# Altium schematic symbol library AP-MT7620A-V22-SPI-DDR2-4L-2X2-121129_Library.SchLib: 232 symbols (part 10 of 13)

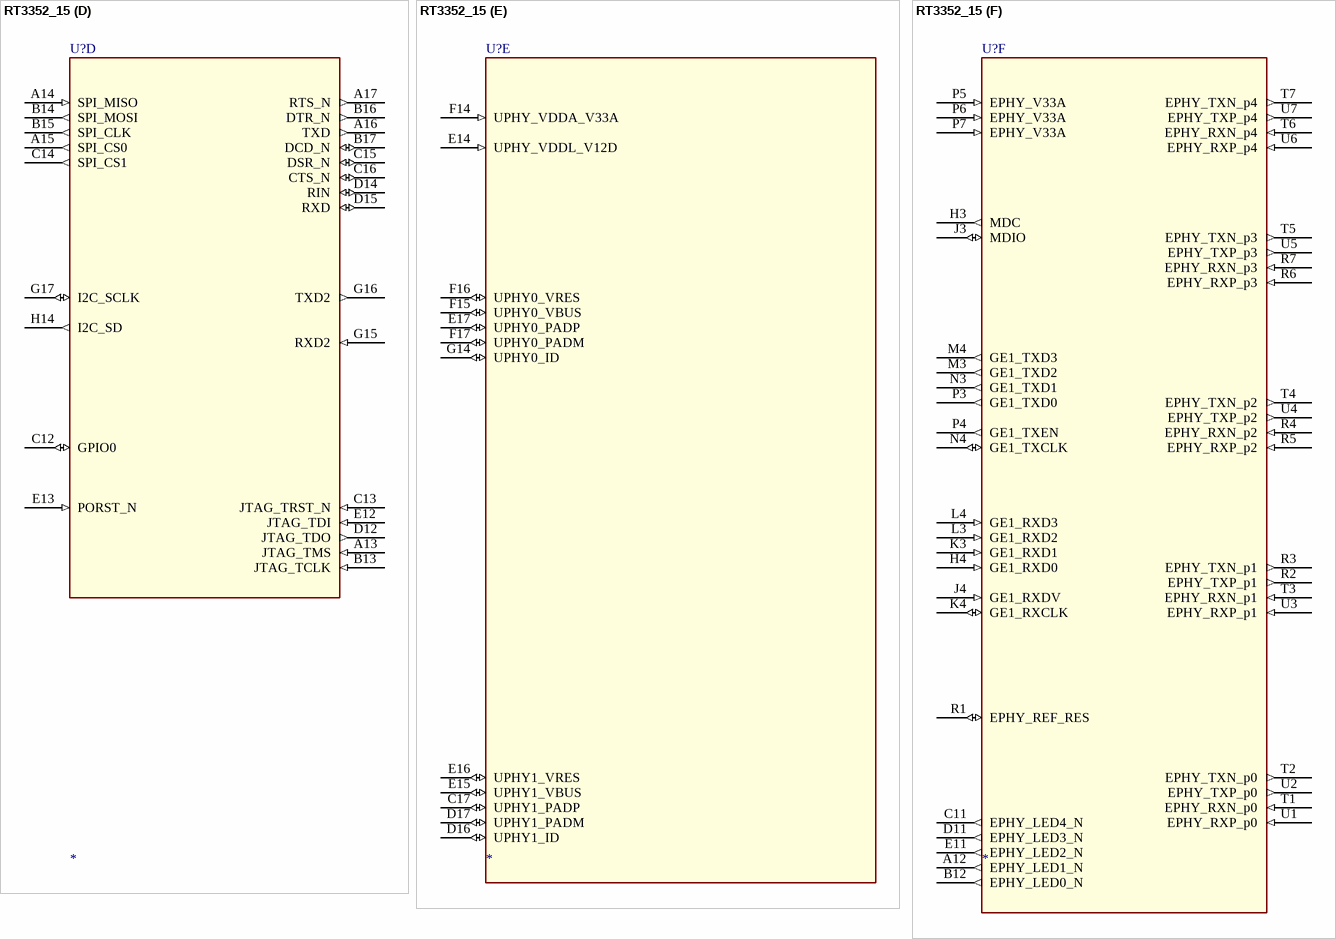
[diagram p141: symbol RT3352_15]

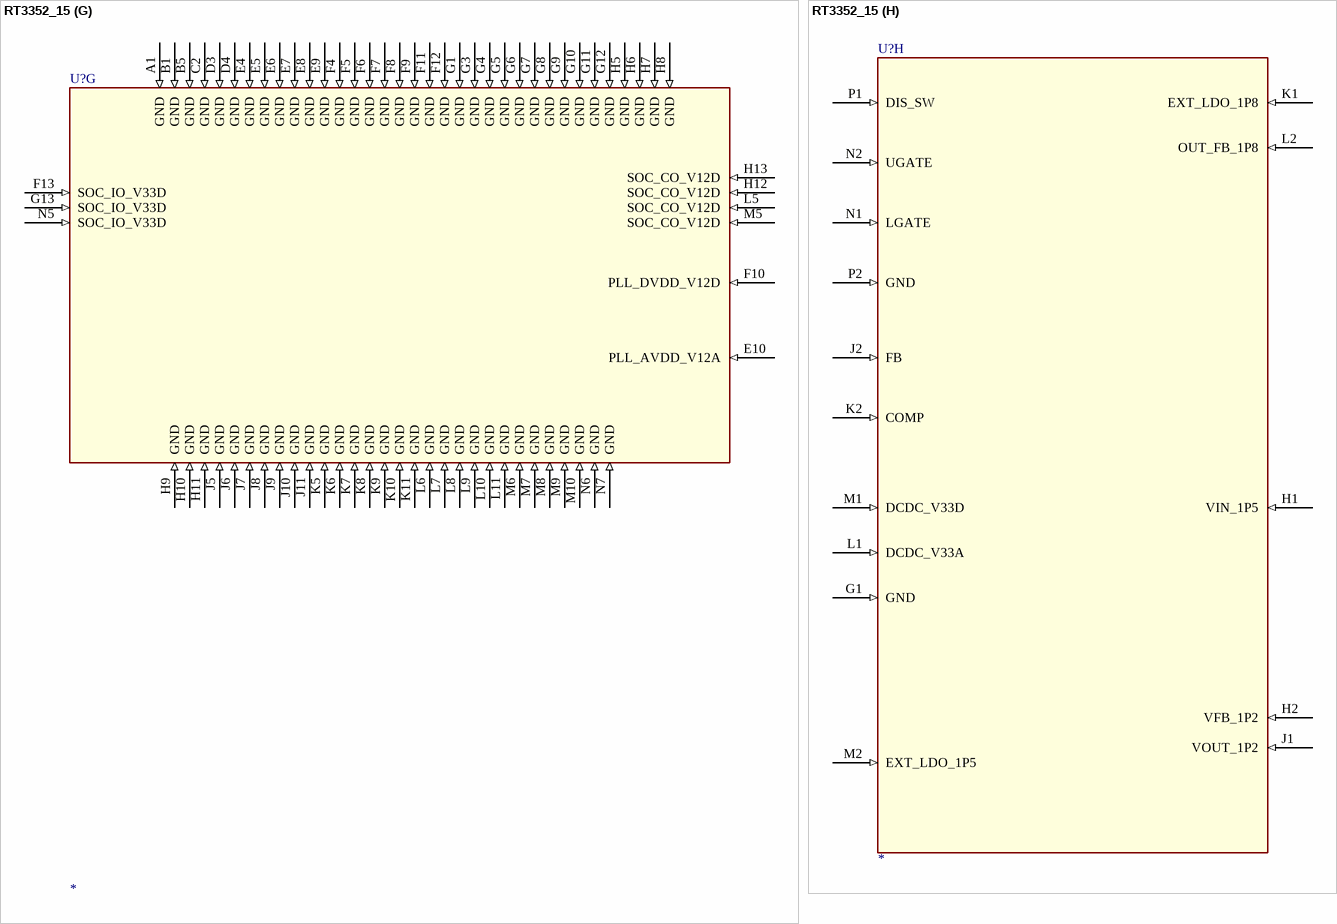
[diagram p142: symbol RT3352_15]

## RT3352_15
designator U?
part A pins: A6 PLL_VC_CAP (in), A7 LDORF_OUT_V12 (out), A8 RF_BB2_V12A (in), A9 ADC_V12 (in), B6 BG_V33A (in), B7 LDORF_IN_VX (in), B8 PLL_X2 (out), B9 PLL_X1 (in), C3 RF0_V12A (in), C4 RF0_IF_V12A (in), C5 VCO_V12A (in), C6 LDOPLL_OUT_V12 (out), C7 BG_RES_12K (in), D5 PLL_V12A (in), D6 RF_BB1_V12A (in), E3 RF1_IF_V12A (in), F3 RF1_V12A (in), G2 RF1_TX_V12A (in)
part B pins: A2 RF0_PA_OUTN (out), A3 RF0_PA_OUTP (out), A4 RF0_2G_INN (in), A5 RF0_2G_INP (in), A10 LNA_PE_G1 (out), A11 ANT_TRNB (out), B2 RF0_PA_V33N (in), B3 RF0_PA_V33P (in), B4 RF0_PA1_V33A (in), B10 LNA_PE_G0 (out), B11 ANT_TRN (out), C1 RF1_2G_INP (in), C8 BASE_TRX_IP (io), C9 BASE_TRX_IN (io), C10 PA_PE_G1 (out), D1 RF1_2G_INN (in), D2 RF1_PA_V33A (in), D7 RF_TSSI_IN (in), D8 BASE_TRX_QP (io), D9 BASE_TRX_QN (io), D10 PA_PE_G0 (out), D13 WLAN_LED_N (out), E1 RF1_PA_OUTP (out), E2 RF1_PA_V33P (in), F1 RF1_PA_OUTN (out), F2 RF1_PA_V33N (in)
part C pins: H15 MD0 (io), H16 MD1 (io), H17 MD2 (io), J12 DDR_IOC_V12D (in), J13 DDR_IOC_V12D (in), J14 MD3 (io), J15 MDQM0 (io), J16 MDQS0 (io), J17 MD6 (io), K12 DDR_IO_V33D (in), K13 DDR_IO_V33D (in), K14 MD8 (io), K15 MD7 (io), K16 MD5 (io), K17 MD4 (io), L12 DDR_IOL_V33D (in), L13 DDR_IOL_V33D (in), L14 MD13 (io), L15 MD10 (io), L16 MD11 (io), L17 MD9 (io), M11 DDR_IO_V33D (in), M12 DDR_IOR_V09D (in), M13 MD15 (io), M14 MD12 (io), M15 MD14 (io), M16 MDQS1 (io), M17 MDQM1 (io), N8 DDR_IO_V33D (in), N9 DDR_IO_V33D (in), N10 DDR_IO_V33D (in), N11 DDR_IO_V33D (in), N12 DDR_IOR_V09D (in), N13 MA0 (io), N14 MA3 (io), N15 MA8 (io), N16 MA10 (io), N17 MA13 (io), P8 MD31 (io), P9 MDQS3 (io), P10 MD22 (io), P11 MDQM2 (io), P12 MD16 (io), P13 MODT (io), P14 MA6 (io), P15 MA4 (io), P16 MA5 (io), P17 MA12 (io), R8 MD30 (io), R9 MD27 (io), R10 MD23 (io), R11 MDQS2 (io), R12 MD17 (io), R13 MCKE (io), R14 MCAS_N (io), R15 MA2 (io), R16 MA7 (io), R17 MA11 (io), T8 MD29 (io), T9 MDQM3 (io), T10 MD24 (io), T11 MD20 (io), T12 MD18 (io), T13 MCK_N (io), T14 MRAS_N (io), T15 MBA0 (io), T16 MA1 (io), T17 MA9 (io), U8 MD28 (io), U9 MD25 (io), U10 MD26 (io), U11 MD21 (io), U12 MD19 (io), U13 MCK_P (io), U14 MWE_N (io), U15 MBA1 (io), U16 MBA2 (io), U17 MCS_N (io)
part D pins: A13 JTAG_TMS (in), A14 SPI_MISO (in), A15 SPI_CS0 (out), A16 TXD (out), A17 RTS_N (out), B13 JTAG_TCLK (in), B14 SPI_MOSI (out), B15 SPI_CLK (out), B16 DTR_N (out), B17 DCD_N (io), C12 GPIO0 (io), C13 JTAG_TRST_N (in), C14 SPI_CS1 (out), C15 DSR_N (io), C16 CTS_N (io), D12 JTAG_TDO (out), D14 RIN (io), D15 RXD (io), E12 JTAG_TDI (in), E13 PORST_N (in), G15 RXD2 (in), G16 TXD2 (out), G17 I2C_SCLK (io), H14 I2C_SD (out)
part E pins: C17 UPHY1_PADP (io), D16 UPHY1_ID (io), D17 UPHY1_PADM (io), E14 UPHY_VDDL_V12D (in), E15 UPHY1_VBUS (io), E16 UPHY1_VRES (io), E17 UPHY0_PADP (io), F14 UPHY_VDDA_V33A (in), F15 UPHY0_VBUS (io), F16 UPHY0_VRES (io), F17 UPHY0_PADM (io), G14 UPHY0_ID (io)
part F pins: A12 EPHY_LED1_N (out), B12 EPHY_LED0_N (out), C11 EPHY_LED4_N (out), D11 EPHY_LED3_N (out), E11 EPHY_LED2_N (out), H3 MDC (out), H4 GE1_RXD0 (in), J3 MDIO (io), J4 GE1_RXDV (in), K3 GE1_RXD1 (in), K4 GE1_RXCLK (io), L3 GE1_RXD2 (in), L4 GE1_RXD3 (in), M3 GE1_TXD2 (out), M4 GE1_TXD3 (out), N3 GE1_TXD1 (out), N4 GE1_TXCLK (io), P3 GE1_TXD0 (out), P4 GE1_TXEN (out), P5 EPHY_V33A (in), P6 EPHY_V33A (in), P7 EPHY_V33A (in), R1 EPHY_REF_RES (io), R2 EPHY_TXP_p1 (out), R3 EPHY_TXN_p1 (out), R4 EPHY_RXN_p2 (in), R5 EPHY_RXP_p2 (in), R6 EPHY_RXP_p3 (in), R7 EPHY_RXN_p3 (in), T1 EPHY_RXN_p0 (in), T2 EPHY_TXN_p0 (out), T3 EPHY_RXN_p1 (in), T4 EPHY_TXN_p2 (out), T5 EPHY_TXN_p3 (out), T6 EPHY_RXN_p4 (in), T7 EPHY_TXN_p4 (out), U1 EPHY_RXP_p0 (in), U2 EPHY_TXP_p0 (out), U3 EPHY_RXP_p1 (in), U4 EPHY_TXP_p2 (out), U5 EPHY_TXP_p3 (out), U6 EPHY_RXP_p4 (in), U7 EPHY_TXP_p4 (out)
part G pins: A1 GND (in), B1 GND (in), B5 GND (in), C2 GND (in), D3 GND (in), D4 GND (in), E4 GND (in), E5 GND (in), E6 GND (in), E7 GND (in), E8 GND (in), E9 GND (in), E10 PLL_AVDD_V12A (in), F4 GND (in), F5 GND (in), F6 GND (in), F7 GND (in), F8 GND (in), F9 GND (in), F10 PLL_DVDD_V12D (in), F11 GND (in), F12 GND (in), F13 SOC_IO_V33D (in), G1 GND (in), G3 GND (in), G4 GND (in), G5 GND (in), G6 GND (in), G7 GND (in), G8 GND (in), G9 GND (in), G10 GND (in), G11 GND (in), G12 GND (in), G13 SOC_IO_V33D (in), H5 GND (in), H6 GND (in), H7 GND (in), H8 GND (in), H9 GND (in), H10 GND (in), H11 GND (in), H12 SOC_CO_V12D (in), H13 SOC_CO_V12D (in), J5 GND (in), J6 GND (in), J7 GND (in), J8 GND (in), J9 GND (in), J10 GND (in), J11 GND (in), K5 GND (in), K6 GND (in), K7 GND (in), K8 GND (in), K9 GND (in), K10 GND (in), K11 GND (in), L5 SOC_CO_V12D (in), L6 GND (in), L7 GND (in), L8 GND (in), L9 GND (in), L10 GND (in), L11 GND (in), M5 SOC_CO_V12D (in), M6 GND (in), M7 GND (in), M8 GND (in), M9 GND (in), M10 GND (in), N5 SOC_IO_V33D (in), N6 GND (in), N7 GND (in)
part H pins: G1 GND (in), H1 VIN_1P5 (in), H2 VFB_1P2 (in), J1 VOUT_1P2 (in), J2 FB (in), K1 EXT_LDO_1P8 (in), K2 COMP (in), L1 DCDC_V33A (in), L2 OUT_FB_1P8 (in), M1 DCDC_V33D (in), M2 EXT_LDO_1P5 (in), N1 LGATE (in), N2 UGATE (in), P1 DIS_SW (in), P2 GND (in)

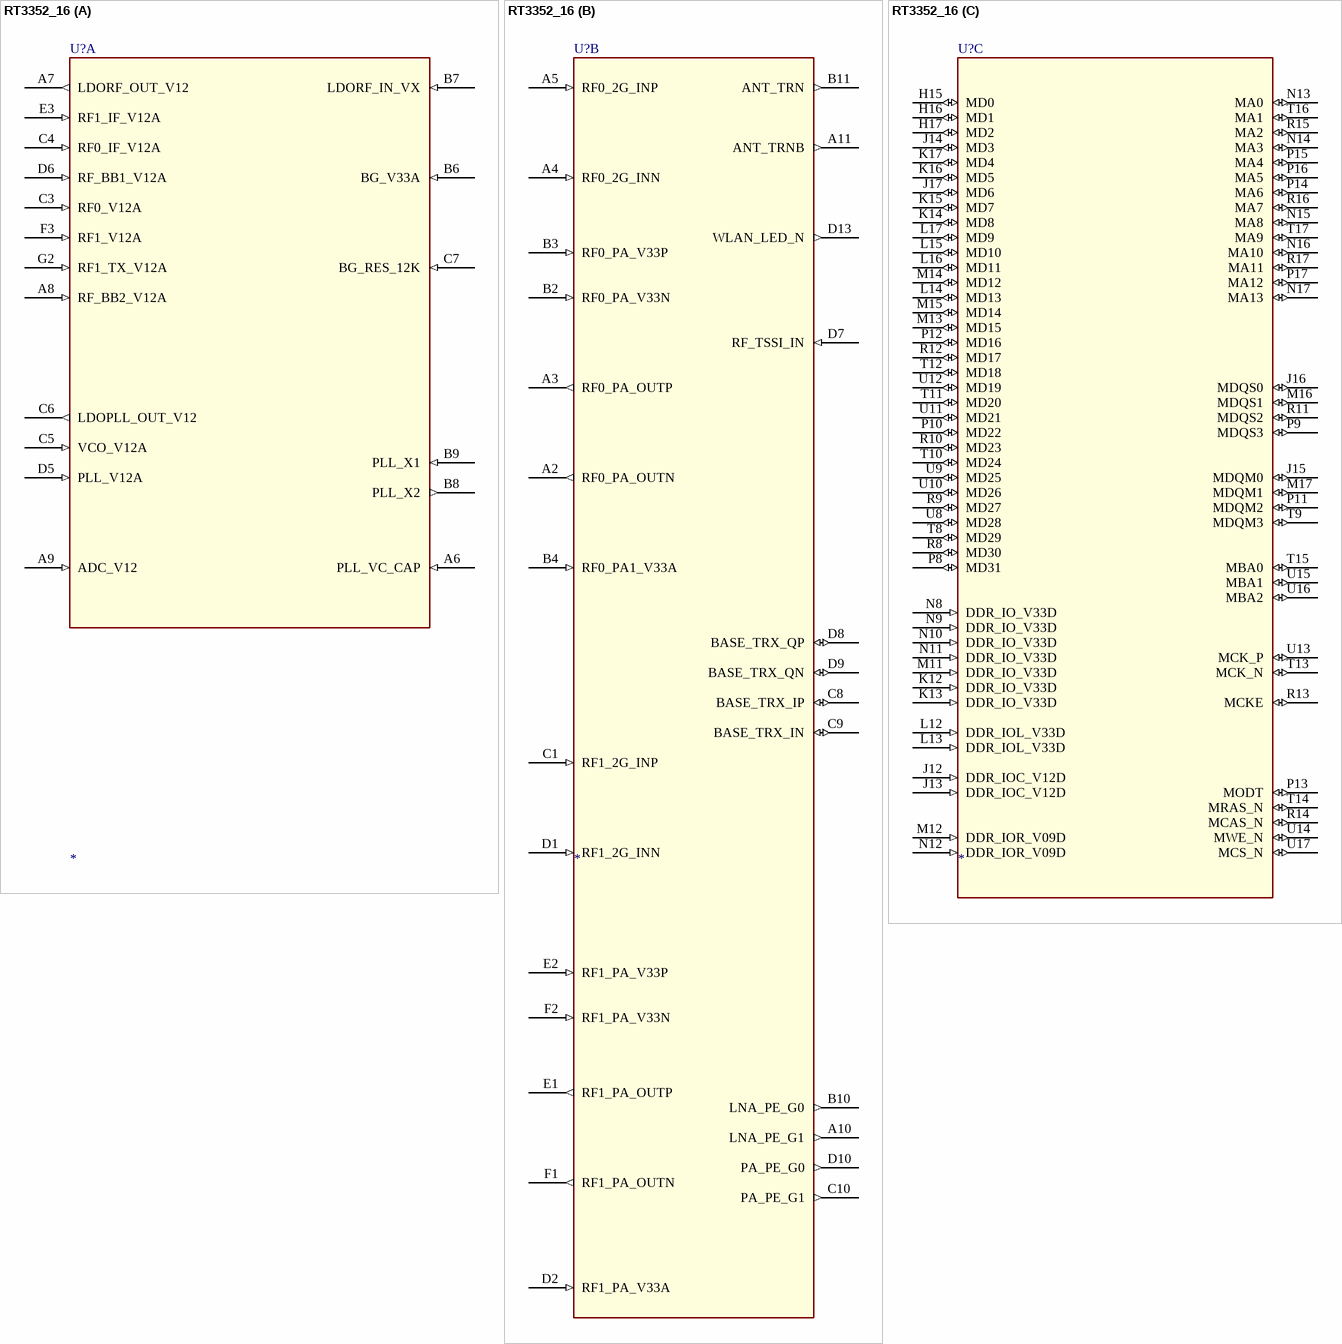
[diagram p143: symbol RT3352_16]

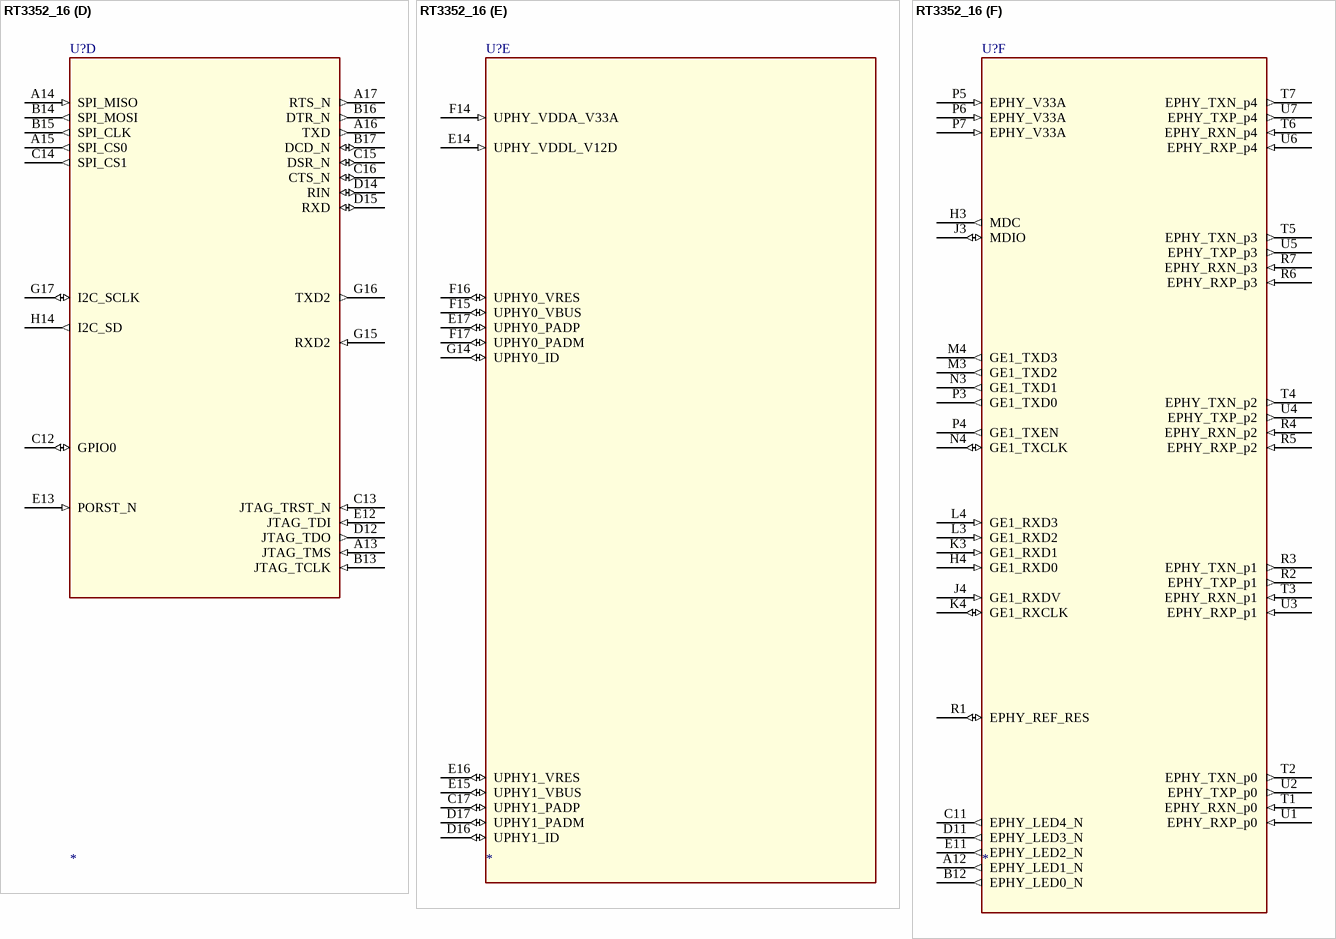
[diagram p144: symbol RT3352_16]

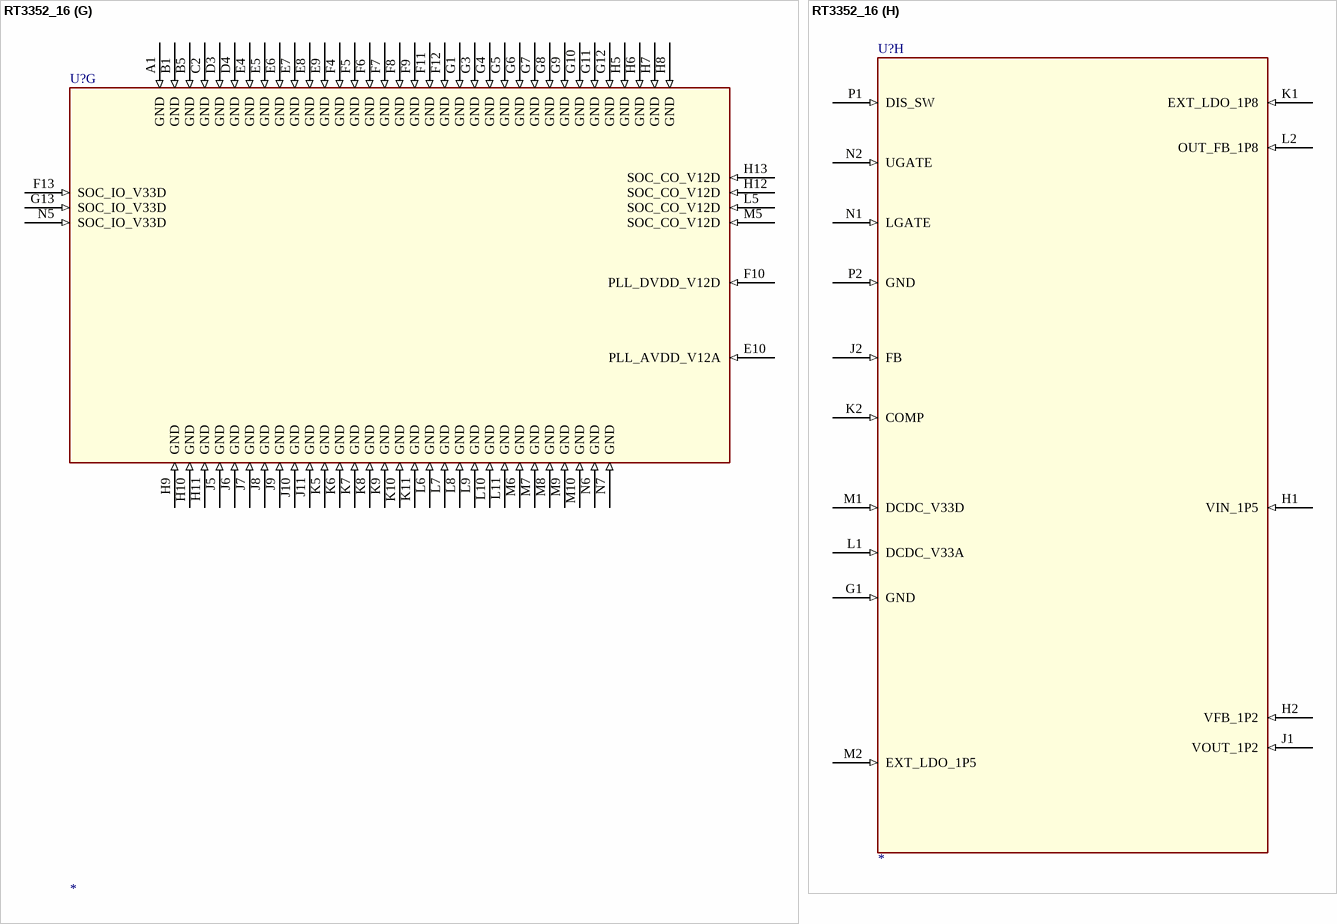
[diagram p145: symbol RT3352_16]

## RT3352_16
designator U?
part A pins: A6 PLL_VC_CAP (in), A7 LDORF_OUT_V12 (out), A8 RF_BB2_V12A (in), A9 ADC_V12 (in), B6 BG_V33A (in), B7 LDORF_IN_VX (in), B8 PLL_X2 (out), B9 PLL_X1 (in), C3 RF0_V12A (in), C4 RF0_IF_V12A (in), C5 VCO_V12A (in), C6 LDOPLL_OUT_V12 (out), C7 BG_RES_12K (in), D5 PLL_V12A (in), D6 RF_BB1_V12A (in), E3 RF1_IF_V12A (in), F3 RF1_V12A (in), G2 RF1_TX_V12A (in)
part B pins: A2 RF0_PA_OUTN (out), A3 RF0_PA_OUTP (out), A4 RF0_2G_INN (in), A5 RF0_2G_INP (in), A10 LNA_PE_G1 (out), A11 ANT_TRNB (out), B2 RF0_PA_V33N (in), B3 RF0_PA_V33P (in), B4 RF0_PA1_V33A (in), B10 LNA_PE_G0 (out), B11 ANT_TRN (out), C1 RF1_2G_INP (in), C8 BASE_TRX_IP (io), C9 BASE_TRX_IN (io), C10 PA_PE_G1 (out), D1 RF1_2G_INN (in), D2 RF1_PA_V33A (in), D7 RF_TSSI_IN (in), D8 BASE_TRX_QP (io), D9 BASE_TRX_QN (io), D10 PA_PE_G0 (out), D13 WLAN_LED_N (out), E1 RF1_PA_OUTP (out), E2 RF1_PA_V33P (in), F1 RF1_PA_OUTN (out), F2 RF1_PA_V33N (in)
part C pins: H15 MD0 (io), H16 MD1 (io), H17 MD2 (io), J12 DDR_IOC_V12D (in), J13 DDR_IOC_V12D (in), J14 MD3 (io), J15 MDQM0 (io), J16 MDQS0 (io), J17 MD6 (io), K12 DDR_IO_V33D (in), K13 DDR_IO_V33D (in), K14 MD8 (io), K15 MD7 (io), K16 MD5 (io), K17 MD4 (io), L12 DDR_IOL_V33D (in), L13 DDR_IOL_V33D (in), L14 MD13 (io), L15 MD10 (io), L16 MD11 (io), L17 MD9 (io), M11 DDR_IO_V33D (in), M12 DDR_IOR_V09D (in), M13 MD15 (io), M14 MD12 (io), M15 MD14 (io), M16 MDQS1 (io), M17 MDQM1 (io), N8 DDR_IO_V33D (in), N9 DDR_IO_V33D (in), N10 DDR_IO_V33D (in), N11 DDR_IO_V33D (in), N12 DDR_IOR_V09D (in), N13 MA0 (io), N14 MA3 (io), N15 MA8 (io), N16 MA10 (io), N17 MA13 (io), P8 MD31 (io), P9 MDQS3 (io), P10 MD22 (io), P11 MDQM2 (io), P12 MD16 (io), P13 MODT (io), P14 MA6 (io), P15 MA4 (io), P16 MA5 (io), P17 MA12 (io), R8 MD30 (io), R9 MD27 (io), R10 MD23 (io), R11 MDQS2 (io), R12 MD17 (io), R13 MCKE (io), R14 MCAS_N (io), R15 MA2 (io), R16 MA7 (io), R17 MA11 (io), T8 MD29 (io), T9 MDQM3 (io), T10 MD24 (io), T11 MD20 (io), T12 MD18 (io), T13 MCK_N (io), T14 MRAS_N (io), T15 MBA0 (io), T16 MA1 (io), T17 MA9 (io), U8 MD28 (io), U9 MD25 (io), U10 MD26 (io), U11 MD21 (io), U12 MD19 (io), U13 MCK_P (io), U14 MWE_N (io), U15 MBA1 (io), U16 MBA2 (io), U17 MCS_N (io)
part D pins: A13 JTAG_TMS (in), A14 SPI_MISO (in), A15 SPI_CS0 (out), A16 TXD (out), A17 RTS_N (out), B13 JTAG_TCLK (in), B14 SPI_MOSI (out), B15 SPI_CLK (out), B16 DTR_N (out), B17 DCD_N (io), C12 GPIO0 (io), C13 JTAG_TRST_N (in), C14 SPI_CS1 (out), C15 DSR_N (io), C16 CTS_N (io), D12 JTAG_TDO (out), D14 RIN (io), D15 RXD (io), E12 JTAG_TDI (in), E13 PORST_N (in), G15 RXD2 (in), G16 TXD2 (out), G17 I2C_SCLK (io), H14 I2C_SD (out)
part E pins: C17 UPHY1_PADP (io), D16 UPHY1_ID (io), D17 UPHY1_PADM (io), E14 UPHY_VDDL_V12D (in), E15 UPHY1_VBUS (io), E16 UPHY1_VRES (io), E17 UPHY0_PADP (io), F14 UPHY_VDDA_V33A (in), F15 UPHY0_VBUS (io), F16 UPHY0_VRES (io), F17 UPHY0_PADM (io), G14 UPHY0_ID (io)
part F pins: A12 EPHY_LED1_N (out), B12 EPHY_LED0_N (out), C11 EPHY_LED4_N (out), D11 EPHY_LED3_N (out), E11 EPHY_LED2_N (out), H3 MDC (out), H4 GE1_RXD0 (in), J3 MDIO (io), J4 GE1_RXDV (in), K3 GE1_RXD1 (in), K4 GE1_RXCLK (io), L3 GE1_RXD2 (in), L4 GE1_RXD3 (in), M3 GE1_TXD2 (out), M4 GE1_TXD3 (out), N3 GE1_TXD1 (out), N4 GE1_TXCLK (io), P3 GE1_TXD0 (out), P4 GE1_TXEN (out), P5 EPHY_V33A (in), P6 EPHY_V33A (in), P7 EPHY_V33A (in), R1 EPHY_REF_RES (io), R2 EPHY_TXP_p1 (out), R3 EPHY_TXN_p1 (out), R4 EPHY_RXN_p2 (in), R5 EPHY_RXP_p2 (in), R6 EPHY_RXP_p3 (in), R7 EPHY_RXN_p3 (in), T1 EPHY_RXN_p0 (in), T2 EPHY_TXN_p0 (out), T3 EPHY_RXN_p1 (in), T4 EPHY_TXN_p2 (out), T5 EPHY_TXN_p3 (out), T6 EPHY_RXN_p4 (in), T7 EPHY_TXN_p4 (out), U1 EPHY_RXP_p0 (in), U2 EPHY_TXP_p0 (out), U3 EPHY_RXP_p1 (in), U4 EPHY_TXP_p2 (out), U5 EPHY_TXP_p3 (out), U6 EPHY_RXP_p4 (in), U7 EPHY_TXP_p4 (out)
part G pins: A1 GND (in), B1 GND (in), B5 GND (in), C2 GND (in), D3 GND (in), D4 GND (in), E4 GND (in), E5 GND (in), E6 GND (in), E7 GND (in), E8 GND (in), E9 GND (in), E10 PLL_AVDD_V12A (in), F4 GND (in), F5 GND (in), F6 GND (in), F7 GND (in), F8 GND (in), F9 GND (in), F10 PLL_DVDD_V12D (in), F11 GND (in), F12 GND (in), F13 SOC_IO_V33D (in), G1 GND (in), G3 GND (in), G4 GND (in), G5 GND (in), G6 GND (in), G7 GND (in), G8 GND (in), G9 GND (in), G10 GND (in), G11 GND (in), G12 GND (in), G13 SOC_IO_V33D (in), H5 GND (in), H6 GND (in), H7 GND (in), H8 GND (in), H9 GND (in), H10 GND (in), H11 GND (in), H12 SOC_CO_V12D (in), H13 SOC_CO_V12D (in), J5 GND (in), J6 GND (in), J7 GND (in), J8 GND (in), J9 GND (in), J10 GND (in), J11 GND (in), K5 GND (in), K6 GND (in), K7 GND (in), K8 GND (in), K9 GND (in), K10 GND (in), K11 GND (in), L5 SOC_CO_V12D (in), L6 GND (in), L7 GND (in), L8 GND (in), L9 GND (in), L10 GND (in), L11 GND (in), M5 SOC_CO_V12D (in), M6 GND (in), M7 GND (in), M8 GND (in), M9 GND (in), M10 GND (in), N5 SOC_IO_V33D (in), N6 GND (in), N7 GND (in)
part H pins: G1 GND (in), H1 VIN_1P5 (in), H2 VFB_1P2 (in), J1 VOUT_1P2 (in), J2 FB (in), K1 EXT_LDO_1P8 (in), K2 COMP (in), L1 DCDC_V33A (in), L2 OUT_FB_1P8 (in), M1 DCDC_V33D (in), M2 EXT_LDO_1P5 (in), N1 LGATE (in), N2 UGATE (in), P1 DIS_SW (in), P2 GND (in)

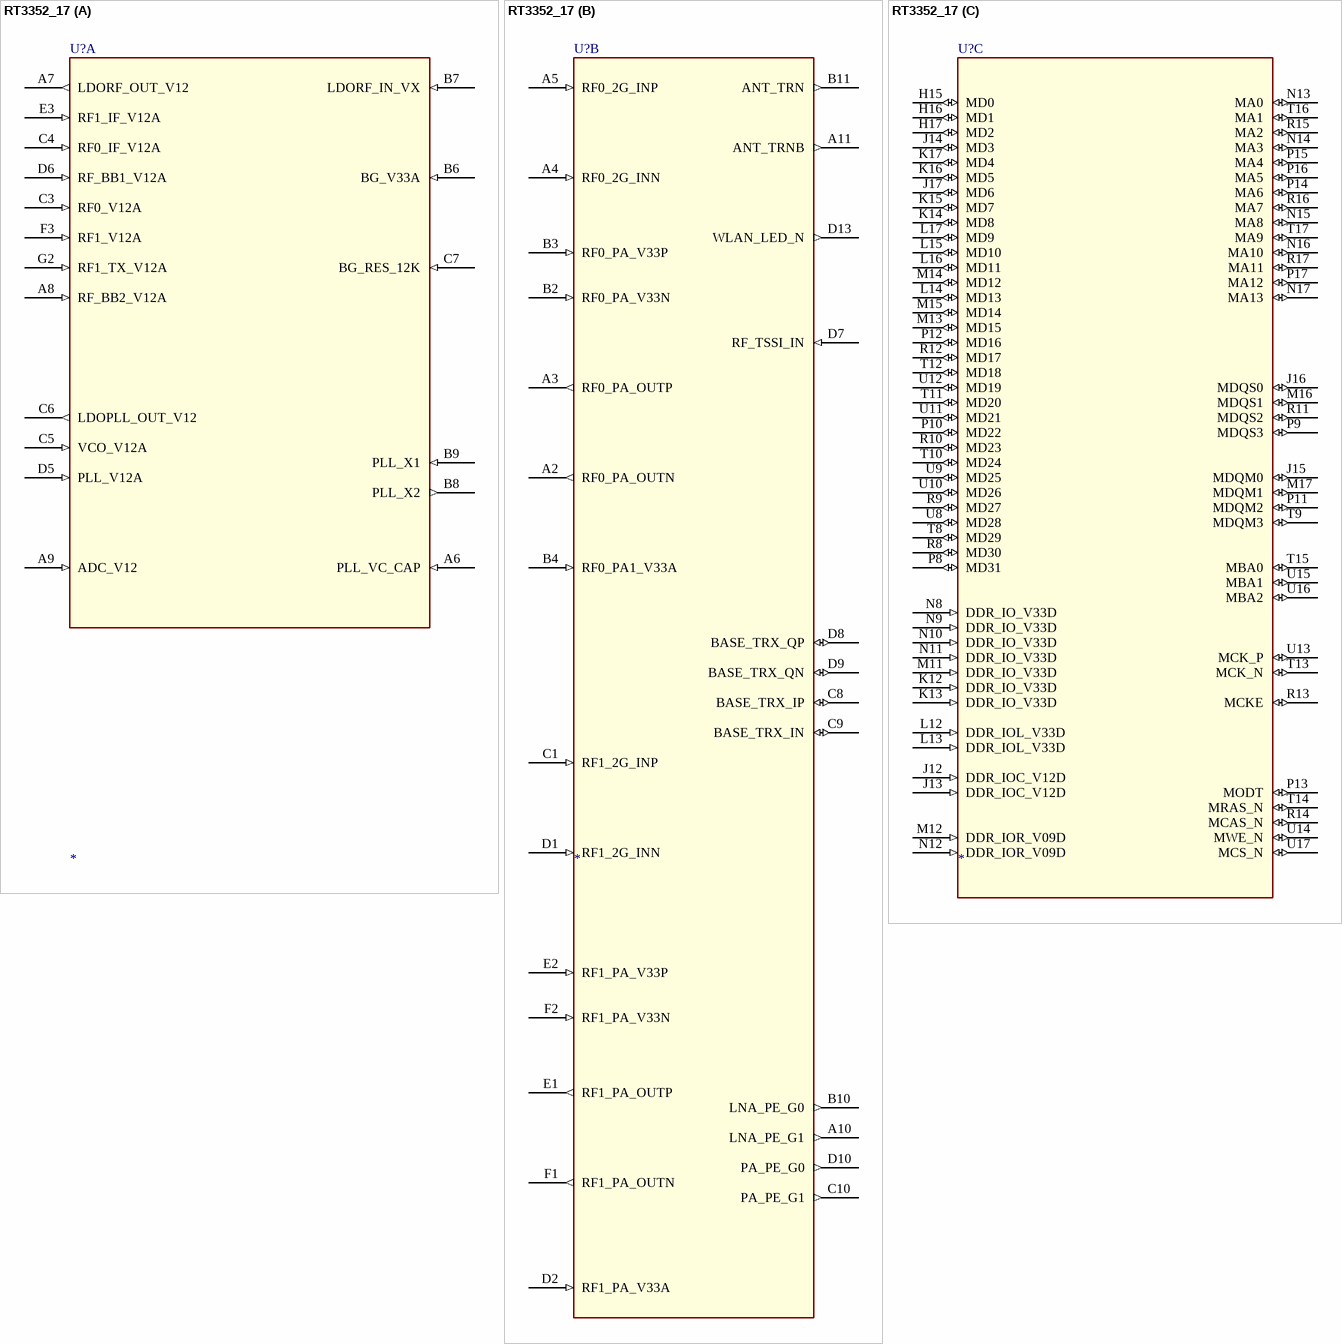
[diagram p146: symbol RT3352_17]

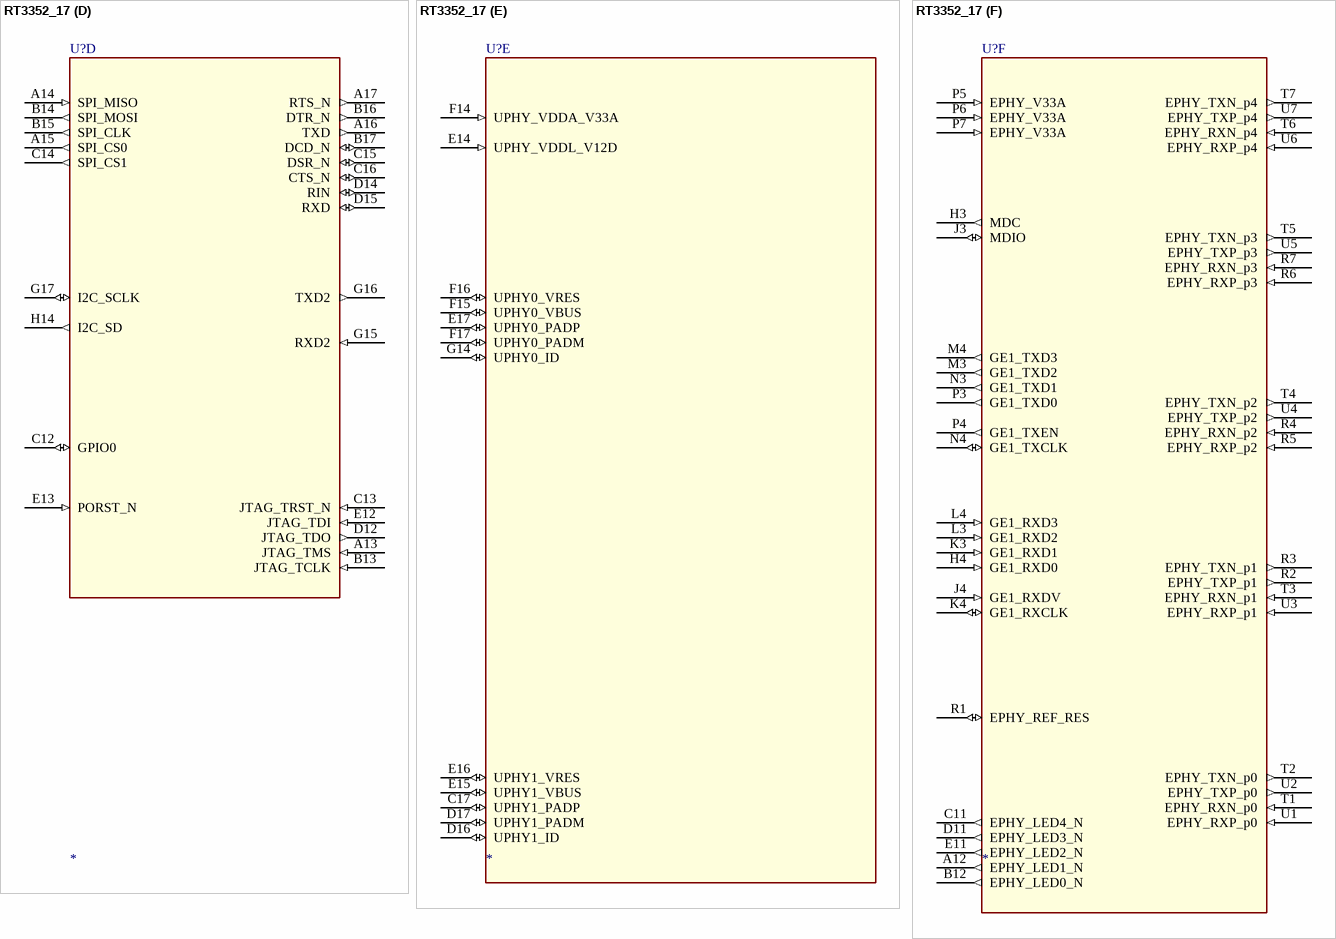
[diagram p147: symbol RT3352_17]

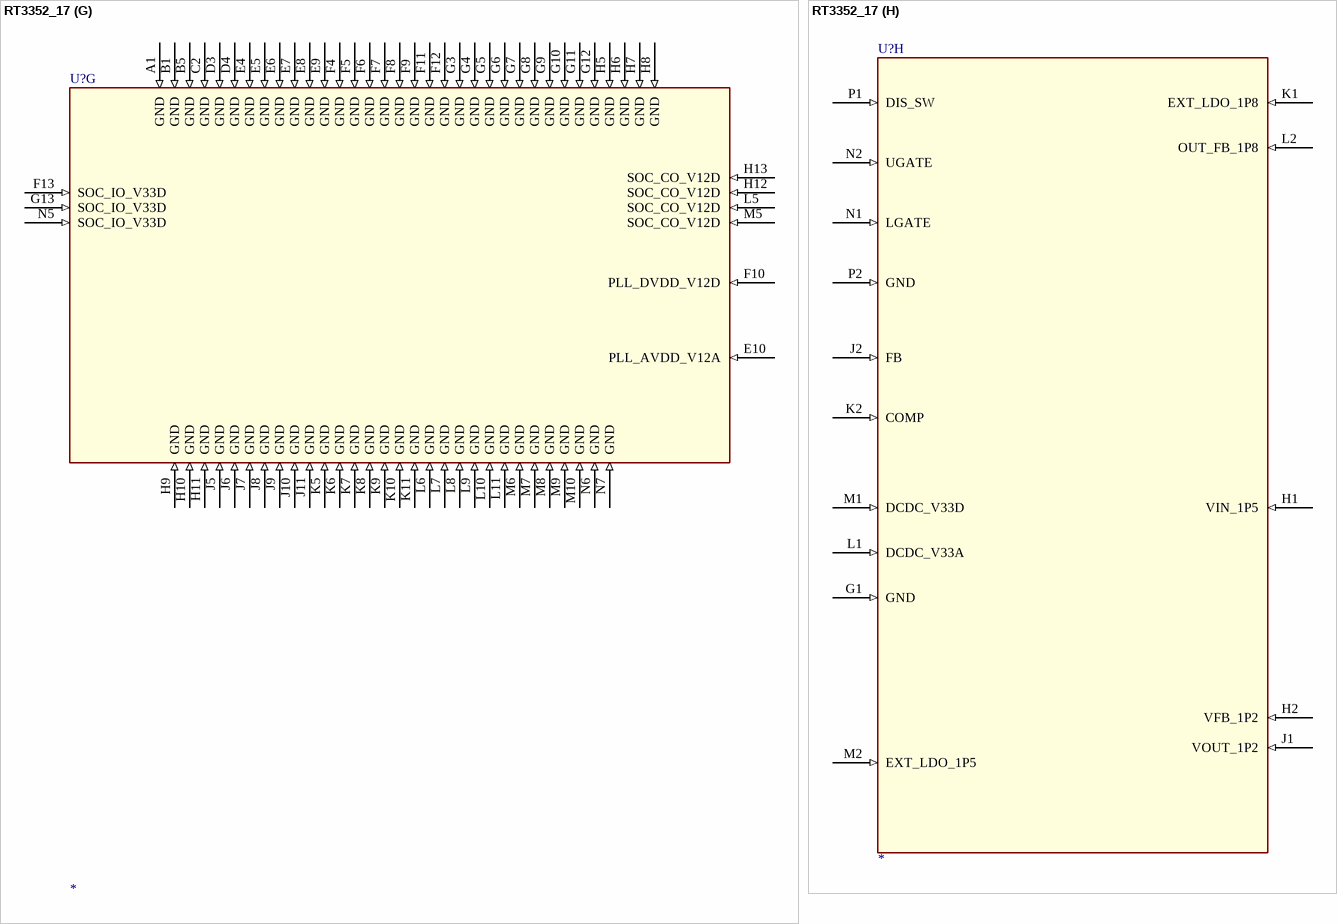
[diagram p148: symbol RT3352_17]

## RT3352_17
designator U?
part A pins: A6 PLL_VC_CAP (in), A7 LDORF_OUT_V12 (out), A8 RF_BB2_V12A (in), A9 ADC_V12 (in), B6 BG_V33A (in), B7 LDORF_IN_VX (in), B8 PLL_X2 (out), B9 PLL_X1 (in), C3 RF0_V12A (in), C4 RF0_IF_V12A (in), C5 VCO_V12A (in), C6 LDOPLL_OUT_V12 (out), C7 BG_RES_12K (in), D5 PLL_V12A (in), D6 RF_BB1_V12A (in), E3 RF1_IF_V12A (in), F3 RF1_V12A (in), G2 RF1_TX_V12A (in)
part B pins: A2 RF0_PA_OUTN (out), A3 RF0_PA_OUTP (out), A4 RF0_2G_INN (in), A5 RF0_2G_INP (in), A10 LNA_PE_G1 (out), A11 ANT_TRNB (out), B2 RF0_PA_V33N (in), B3 RF0_PA_V33P (in), B4 RF0_PA1_V33A (in), B10 LNA_PE_G0 (out), B11 ANT_TRN (out), C1 RF1_2G_INP (in), C8 BASE_TRX_IP (io), C9 BASE_TRX_IN (io), C10 PA_PE_G1 (out), D1 RF1_2G_INN (in), D2 RF1_PA_V33A (in), D7 RF_TSSI_IN (in), D8 BASE_TRX_QP (io), D9 BASE_TRX_QN (io), D10 PA_PE_G0 (out), D13 WLAN_LED_N (out), E1 RF1_PA_OUTP (out), E2 RF1_PA_V33P (in), F1 RF1_PA_OUTN (out), F2 RF1_PA_V33N (in)
part C pins: H15 MD0 (io), H16 MD1 (io), H17 MD2 (io), J12 DDR_IOC_V12D (in), J13 DDR_IOC_V12D (in), J14 MD3 (io), J15 MDQM0 (io), J16 MDQS0 (io), J17 MD6 (io), K12 DDR_IO_V33D (in), K13 DDR_IO_V33D (in), K14 MD8 (io), K15 MD7 (io), K16 MD5 (io), K17 MD4 (io), L12 DDR_IOL_V33D (in), L13 DDR_IOL_V33D (in), L14 MD13 (io), L15 MD10 (io), L16 MD11 (io), L17 MD9 (io), M11 DDR_IO_V33D (in), M12 DDR_IOR_V09D (in), M13 MD15 (io), M14 MD12 (io), M15 MD14 (io), M16 MDQS1 (io), M17 MDQM1 (io), N8 DDR_IO_V33D (in), N9 DDR_IO_V33D (in), N10 DDR_IO_V33D (in), N11 DDR_IO_V33D (in), N12 DDR_IOR_V09D (in), N13 MA0 (io), N14 MA3 (io), N15 MA8 (io), N16 MA10 (io), N17 MA13 (io), P8 MD31 (io), P9 MDQS3 (io), P10 MD22 (io), P11 MDQM2 (io), P12 MD16 (io), P13 MODT (io), P14 MA6 (io), P15 MA4 (io), P16 MA5 (io), P17 MA12 (io), R8 MD30 (io), R9 MD27 (io), R10 MD23 (io), R11 MDQS2 (io), R12 MD17 (io), R13 MCKE (io), R14 MCAS_N (io), R15 MA2 (io), R16 MA7 (io), R17 MA11 (io), T8 MD29 (io), T9 MDQM3 (io), T10 MD24 (io), T11 MD20 (io), T12 MD18 (io), T13 MCK_N (io), T14 MRAS_N (io), T15 MBA0 (io), T16 MA1 (io), T17 MA9 (io), U8 MD28 (io), U9 MD25 (io), U10 MD26 (io), U11 MD21 (io), U12 MD19 (io), U13 MCK_P (io), U14 MWE_N (io), U15 MBA1 (io), U16 MBA2 (io), U17 MCS_N (io)
part D pins: A13 JTAG_TMS (in), A14 SPI_MISO (in), A15 SPI_CS0 (out), A16 TXD (out), A17 RTS_N (out), B13 JTAG_TCLK (in), B14 SPI_MOSI (out), B15 SPI_CLK (out), B16 DTR_N (out), B17 DCD_N (io), C12 GPIO0 (io), C13 JTAG_TRST_N (in), C14 SPI_CS1 (out), C15 DSR_N (io), C16 CTS_N (io), D12 JTAG_TDO (out), D14 RIN (io), D15 RXD (io), E12 JTAG_TDI (in), E13 PORST_N (in), G15 RXD2 (in), G16 TXD2 (out), G17 I2C_SCLK (io), H14 I2C_SD (out)
part E pins: C17 UPHY1_PADP (io), D16 UPHY1_ID (io), D17 UPHY1_PADM (io), E14 UPHY_VDDL_V12D (in), E15 UPHY1_VBUS (io), E16 UPHY1_VRES (io), E17 UPHY0_PADP (io), F14 UPHY_VDDA_V33A (in), F15 UPHY0_VBUS (io), F16 UPHY0_VRES (io), F17 UPHY0_PADM (io), G14 UPHY0_ID (io)
part F pins: A12 EPHY_LED1_N (out), B12 EPHY_LED0_N (out), C11 EPHY_LED4_N (out), D11 EPHY_LED3_N (out), E11 EPHY_LED2_N (out), H3 MDC (out), H4 GE1_RXD0 (in), J3 MDIO (io), J4 GE1_RXDV (in), K3 GE1_RXD1 (in), K4 GE1_RXCLK (io), L3 GE1_RXD2 (in), L4 GE1_RXD3 (in), M3 GE1_TXD2 (out), M4 GE1_TXD3 (out), N3 GE1_TXD1 (out), N4 GE1_TXCLK (io), P3 GE1_TXD0 (out), P4 GE1_TXEN (out), P5 EPHY_V33A (in), P6 EPHY_V33A (in), P7 EPHY_V33A (in), R1 EPHY_REF_RES (io), R2 EPHY_TXP_p1 (out), R3 EPHY_TXN_p1 (out), R4 EPHY_RXN_p2 (in), R5 EPHY_RXP_p2 (in), R6 EPHY_RXP_p3 (in), R7 EPHY_RXN_p3 (in), T1 EPHY_RXN_p0 (in), T2 EPHY_TXN_p0 (out), T3 EPHY_RXN_p1 (in), T4 EPHY_TXN_p2 (out), T5 EPHY_TXN_p3 (out), T6 EPHY_RXN_p4 (in), T7 EPHY_TXN_p4 (out), U1 EPHY_RXP_p0 (in), U2 EPHY_TXP_p0 (out), U3 EPHY_RXP_p1 (in), U4 EPHY_TXP_p2 (out), U5 EPHY_TXP_p3 (out), U6 EPHY_RXP_p4 (in), U7 EPHY_TXP_p4 (out)
part G pins: A1 GND (in), B1 GND (in), B5 GND (in), C2 GND (in), D3 GND (in), D4 GND (in), E4 GND (in), E5 GND (in), E6 GND (in), E7 GND (in), E8 GND (in), E9 GND (in), E10 PLL_AVDD_V12A (in), F4 GND (in), F5 GND (in), F6 GND (in), F7 GND (in), F8 GND (in), F9 GND (in), F10 PLL_DVDD_V12D (in), F11 GND (in), F12 GND (in), F13 SOC_IO_V33D (in), G3 GND (in), G4 GND (in), G5 GND (in), G6 GND (in), G7 GND (in), G8 GND (in), G9 GND (in), G10 GND (in), G11 GND (in), G12 GND (in), G13 SOC_IO_V33D (in), H5 GND (in), H6 GND (in), H7 GND (in), H8 GND (in), H9 GND (in), H10 GND (in), H11 GND (in), H12 SOC_CO_V12D (in), H13 SOC_CO_V12D (in), J5 GND (in), J6 GND (in), J7 GND (in), J8 GND (in), J9 GND (in), J10 GND (in), J11 GND (in), K5 GND (in), K6 GND (in), K7 GND (in), K8 GND (in), K9 GND (in), K10 GND (in), K11 GND (in), L5 SOC_CO_V12D (in), L6 GND (in), L7 GND (in), L8 GND (in), L9 GND (in), L10 GND (in), L11 GND (in), M5 SOC_CO_V12D (in), M6 GND (in), M7 GND (in), M8 GND (in), M9 GND (in), M10 GND (in), N5 SOC_IO_V33D (in), N6 GND (in), N7 GND (in)
part H pins: G1 GND (in), H1 VIN_1P5 (in), H2 VFB_1P2 (in), J1 VOUT_1P2 (in), J2 FB (in), K1 EXT_LDO_1P8 (in), K2 COMP (in), L1 DCDC_V33A (in), L2 OUT_FB_1P8 (in), M1 DCDC_V33D (in), M2 EXT_LDO_1P5 (in), N1 LGATE (in), N2 UGATE (in), P1 DIS_SW (in), P2 GND (in)

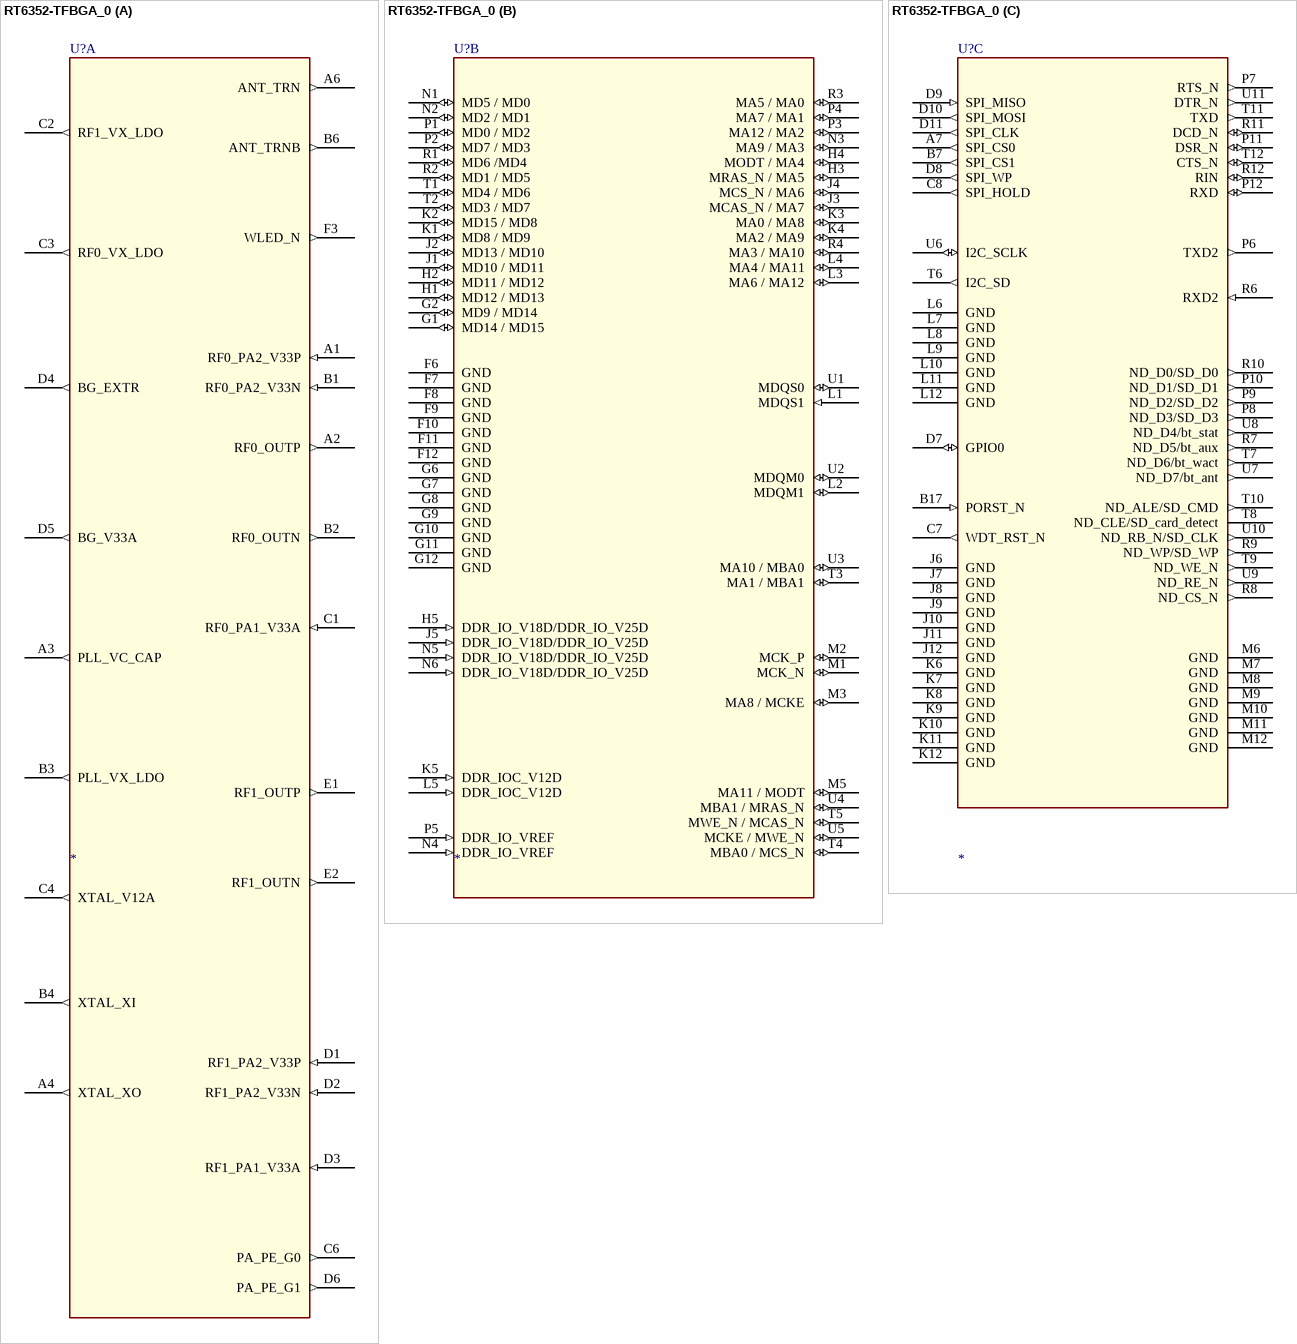
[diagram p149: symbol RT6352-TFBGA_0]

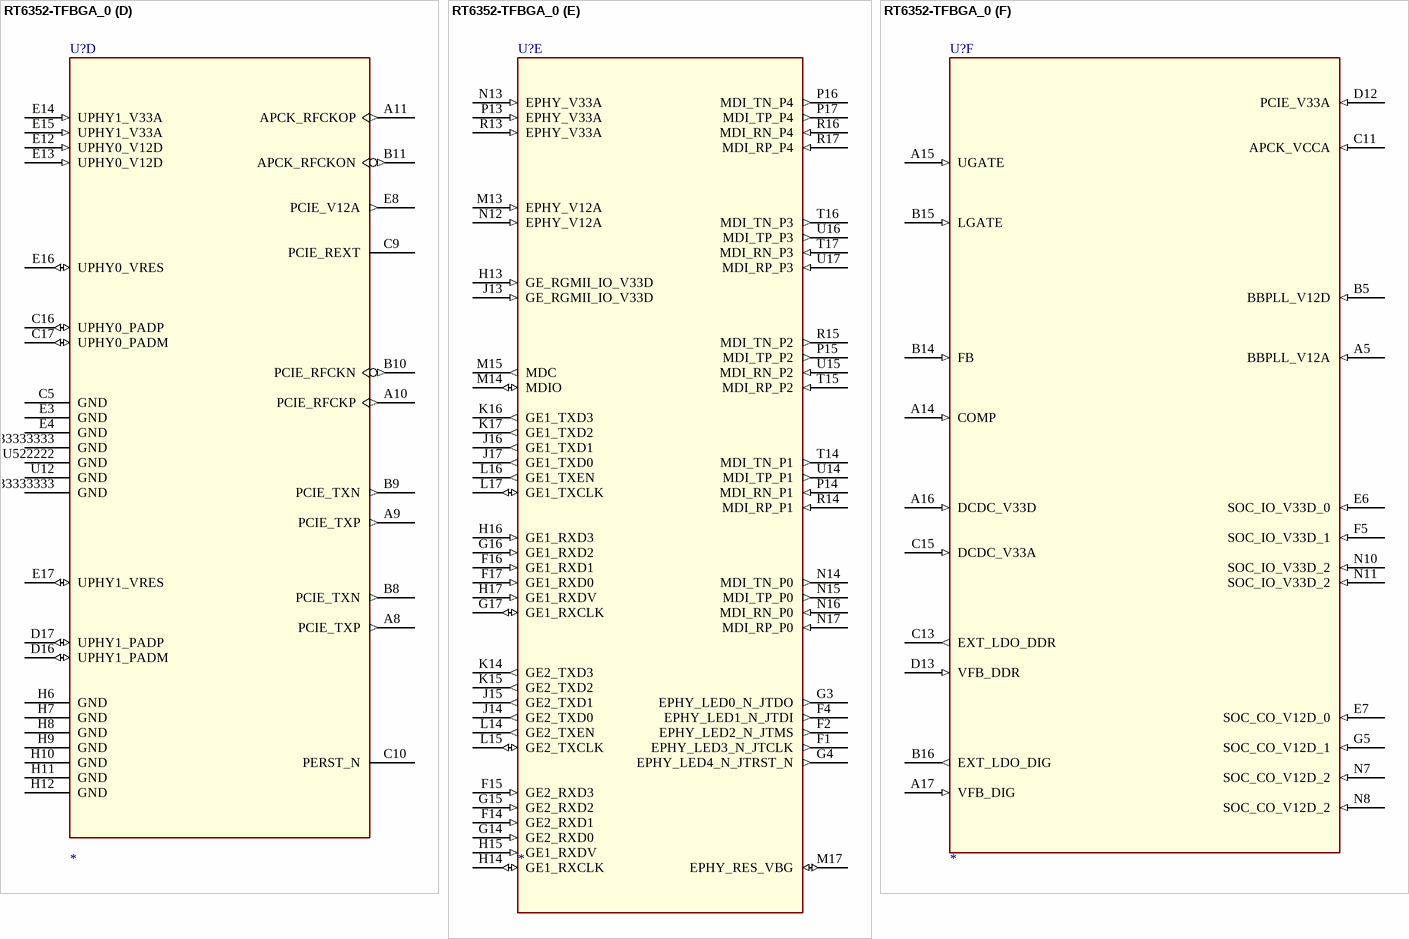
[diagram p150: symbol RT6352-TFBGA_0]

## RT6352-TFBGA_0
designator U?
footprint RT6352/BGA289/P0.65/12X12
part A pins: A1 RF0_PA2_V33P (in), A2 RF0_OUTP (out), A3 PLL_VC_CAP (out), A4 XTAL_XO (out), A6 ANT_TRN (out), B1 RF0_PA2_V33N (in), B2 RF0_OUTN (out), B3 PLL_VX_LDO (out), B4 XTAL_XI (out), B6 ANT_TRNB (out), C1 RF0_PA1_V33A (in), C2 RF1_VX_LDO (out), C3 RF0_VX_LDO (out), C4 XTAL_V12A (out), C6 PA_PE_G0 (out), D1 RF1_PA2_V33P (in), D2 RF1_PA2_V33N (in), D3 RF1_PA1_V33A (in), D4 BG_EXTR (out), D5 BG_V33A (out), D6 PA_PE_G1 (out), E1 RF1_OUTP (out), E2 RF1_OUTN (out), F3 WLED_N (out)
part B pins: F6 GND (power), F7 GND (power), F8 GND (power), F9 GND (power), F10 GND (power), F11 GND (power), F12 GND (power), G1 MD14 / MD15 (io), G2 MD9 / MD14 (io), G6 GND (power), G7 GND (power), G8 GND (power), G9 GND (power), G10 GND (power), G11 GND (power), G12 GND (power), H1 MD12 / MD13 (io), H2 MD11 / MD12 (io), H3 MRAS_N / MA5 (io), H4 MODT / MA4 (io), H5 DDR_IO_V18D/DDR_IO_V25D (in), J1 MD10 / MD11 (io), J2 MD13 / MD10 (io), J3 MCAS_N / MA7 (io), J4 MCS_N / MA6 (io), J5 DDR_IO_V18D/DDR_IO_V25D (in), K1 MD8 / MD9 (io), K2 MD15 / MD8 (io), K3 MA0 / MA8 (io), K4 MA2 / MA9 (io), K5 DDR_IOC_V12D (in), L1 MDQS1 (in), L2 MDQM1 (io), L3 MA6 / MA12 (io), L4 MA4 / MA11 (io), L5 DDR_IOC_V12D (in), M1 MCK_N (io), M2 MCK_P (io), M3 MA8 / MCKE (io), M5 MA11 / MODT (io), N1 MD5 / MD0 (io), N2 MD2 / MD1 (io), N3 MA9 / MA3 (io), N4 DDR_IO_VREF (in), N5 DDR_IO_V18D/DDR_IO_V25D (in), N6 DDR_IO_V18D/DDR_IO_V25D (in), P1 MD0 / MD2 (io), P2 MD7 / MD3 (io), P3 MA12 / MA2 (io), P4 MA7 / MA1 (io), P5 DDR_IO_VREF (in), R1 MD6 /MD4 (io), R2 MD1 / MD5 (io), R3 MA5 / MA0 (io), R4 MA3 / MA10 (io), T1 MD4 / MD6 (io), T2 MD3 / MD7 (io), T3 MA1 / MBA1 (io), T4 MBA0 / MCS_N (io), T5 MWE_N / MCAS_N (io), U1 MDQS0 (io), U2 MDQM0 (io), U3 MA10 / MBA0 (io), U4 MBA1 / MRAS_N (io), U5 MCKE / MWE_N (io)
part C pins: A7 SPI_CS0 (out), B7 SPI_CS1 (out), B17 PORST_N (in), C7 WDT_RST_N (out), C8 SPI_HOLD (out), D7 GPIO0 (io), D8 SPI_WP (out), D9 SPI_MISO (in), D10 SPI_MOSI (out), D11 SPI_CLK (out), J6 GND (power), J7 GND (power), J8 GND (power), J9 GND (power), J10 GND (power), J11 GND (power), J12 GND (power), K6 GND (power), K7 GND (power), K8 GND (power), K9 GND (power), K10 GND (power), K11 GND (power), K12 GND (power), L6 GND (power), L7 GND (power), L8 GND (power), L9 GND (power), L10 GND (power), L11 GND (power), L12 GND (power), M6 GND (power), M7 GND (power), M8 GND (power), M9 GND (power), M10 GND (power), M11 GND (power), M12 GND (power), P6 TXD2 (out), P7 RTS_N (out), P8 ND_D3/SD_D3 (out), P9 ND_D2/SD_D2 (out), P10 ND_D1/SD_D1 (out), P11 DSR_N (io), P12 RXD (io), R6 RXD2 (in), R7 ND_D5/bt_aux (out), R8 ND_CS_N (out), R9 ND_WP/SD_WP (out), R10 ND_D0/SD_D0 (out), R11 DCD_N (io), R12 RIN (io), T6 I2C_SD (out), T7 ND_D6/bt_wact (out), T8 ND_CLE/SD_card_detect, T9 ND_WE_N (out), T10 ND_ALE/SD_CMD (out), T11 TXD (out), T12 CTS_N (io), U6 I2C_SCLK (io), U7 ND_D7/bt_ant (out), U8 ND_D4/bt_stat (out), U9 ND_RE_N (out), U10 ND_RB_N/SD_CLK (out), U11 DTR_N (out)
part D pins: A8 PCIE_TXP (out), A9 PCIE_TXP (out), A10 PCIE_RFCKP (out), A11 APCK_RFCKOP (out), B8 PCIE_TXN (out), B9 PCIE_TXN (out), B10 PCIE_RFCKN (out), B11 APCK_RFCKON (out), C5 GND (power), C9 PCIE_REXT, C10 PERST_N, C16 UPHY0_PADP (io), C17 UPHY0_PADM (io), D16 UPHY1_PADM (io), D17 UPHY1_PADP (io), E3 GND (power), E4 GND (power), E8 PCIE_V12A (out), E12 UPHY0_V12D (in), E13 UPHY0_V12D (in), E14 UPHY1_V33A (in), E15 UPHY1_V33A (in), E16 UPHY0_VRES (io), E17 UPHY1_VRES (io), H6 GND (power), H7 GND (power), H8 GND (power), H9 GND (power), H10 GND (power), H11 GND (power), H12 GND (power), K33333333 GND (power), R17333333333 GND (power), U12 GND (power), U522222 GND (power)
part E pins: F1 EPHY_LED3_N_JTCLK (out), F2 EPHY_LED2_N_JTMS (out), F4 EPHY_LED1_N_JTDI (out), F14 GE2_RXD1 (in), F15 GE2_RXD3 (in), F16 GE1_RXD1 (in), F17 GE1_RXD0 (in), G3 EPHY_LED0_N_JTDO (out), G4 EPHY_LED4_N_JTRST_N (out), G14 GE2_RXD0 (in), G15 GE2_RXD2 (in), G16 GE1_RXD2 (in), G17 GE1_RXCLK (io), H13 GE_RGMII_IO_V33D (in), H14 GE1_RXCLK (io), H15 GE1_RXDV (in), H16 GE1_RXD3 (in), H17 GE1_RXDV (in), J13 GE_RGMII_IO_V33D (in), J14 GE2_TXD0 (out), J15 GE2_TXD1 (out), J16 GE1_TXD1 (out), J17 GE1_TXD0 (out), K14 GE2_TXD3 (out), K15 GE2_TXD2 (out), K16 GE1_TXD3 (out), K17 GE1_TXD2 (out), L14 GE2_TXEN (out), L15 GE2_TXCLK (io), L16 GE1_TXEN (out), L17 GE1_TXCLK (io), M13 EPHY_V12A (in), M14 MDIO (io), M15 MDC (out), M17 EPHY_RES_VBG (io), N12 EPHY_V12A (in), N13 EPHY_V33A (in), N14 MDI_TN_P0 (out), N15 MDI_TP_P0 (out), N16 MDI_RN_P0 (in), N17 MDI_RP_P0 (in), P13 EPHY_V33A (in), P14 MDI_RN_P1 (in), P15 MDI_TP_P2 (out), P16 MDI_TN_P4 (out), P17 MDI_TP_P4 (out), R13 EPHY_V33A (in), R14 MDI_RP_P1 (in), R15 MDI_TN_P2 (out), R16 MDI_RN_P4 (in), R17 MDI_RP_P4 (in), T14 MDI_TN_P1 (out), T15 MDI_RP_P2 (in), T16 MDI_TN_P3 (out), T17 MDI_RN_P3 (in), U14 MDI_TP_P1 (out), U15 MDI_RN_P2 (in), U16 MDI_TP_P3 (out), U17 MDI_RP_P3 (in)
part F pins: A5 BBPLL_V12A (in), A14 COMP (in), A15 UGATE (in), A16 DCDC_V33D (in), A17 VFB_DIG (in), B5 BBPLL_V12D (in), B14 FB (in), B15 LGATE (in), B16 EXT_LDO_DIG (out), C11 APCK_VCCA (in), C13 EXT_LDO_DDR (out), C15 DCDC_V33A (in), D12 PCIE_V33A (in), D13 VFB_DDR (in), E6 SOC_IO_V33D_0 (in), E7 SOC_CO_V12D_0 (in), F5 SOC_IO_V33D_1 (in), G5 SOC_CO_V12D_1 (in), N7 SOC_CO_V12D_2 (in), N8 SOC_CO_V12D_2 (in), N10 SOC_IO_V33D_2 (in), N11 SOC_IO_V33D_2 (in)

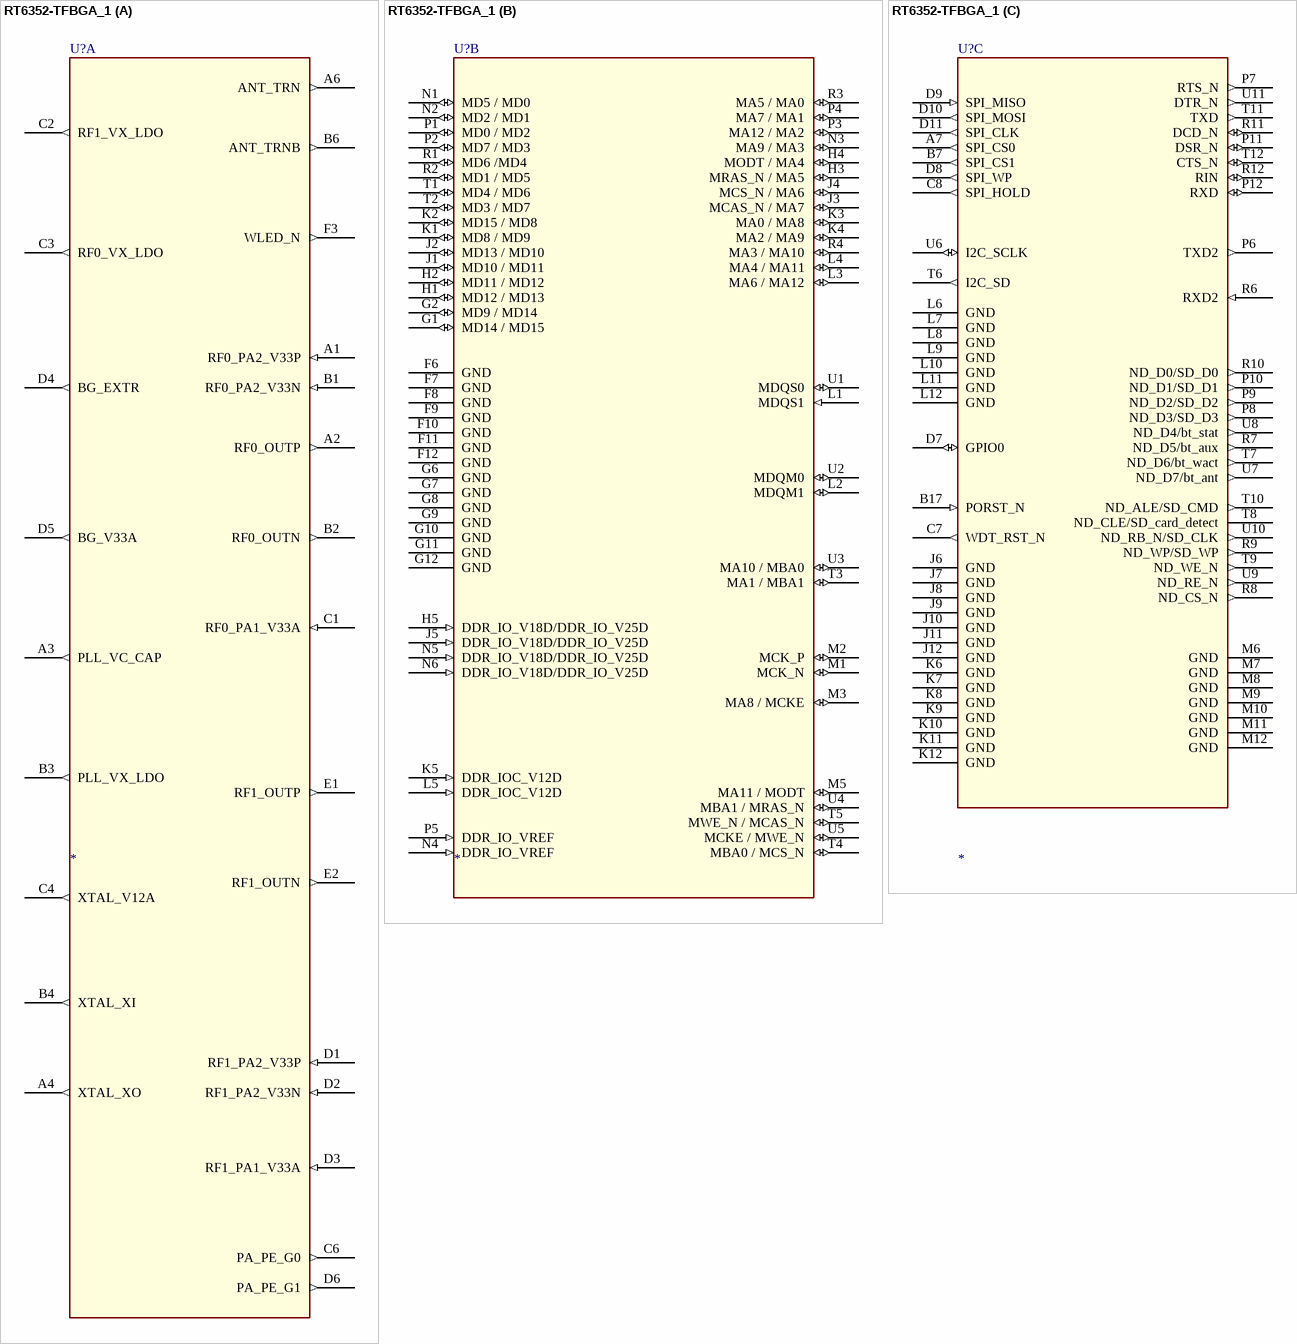
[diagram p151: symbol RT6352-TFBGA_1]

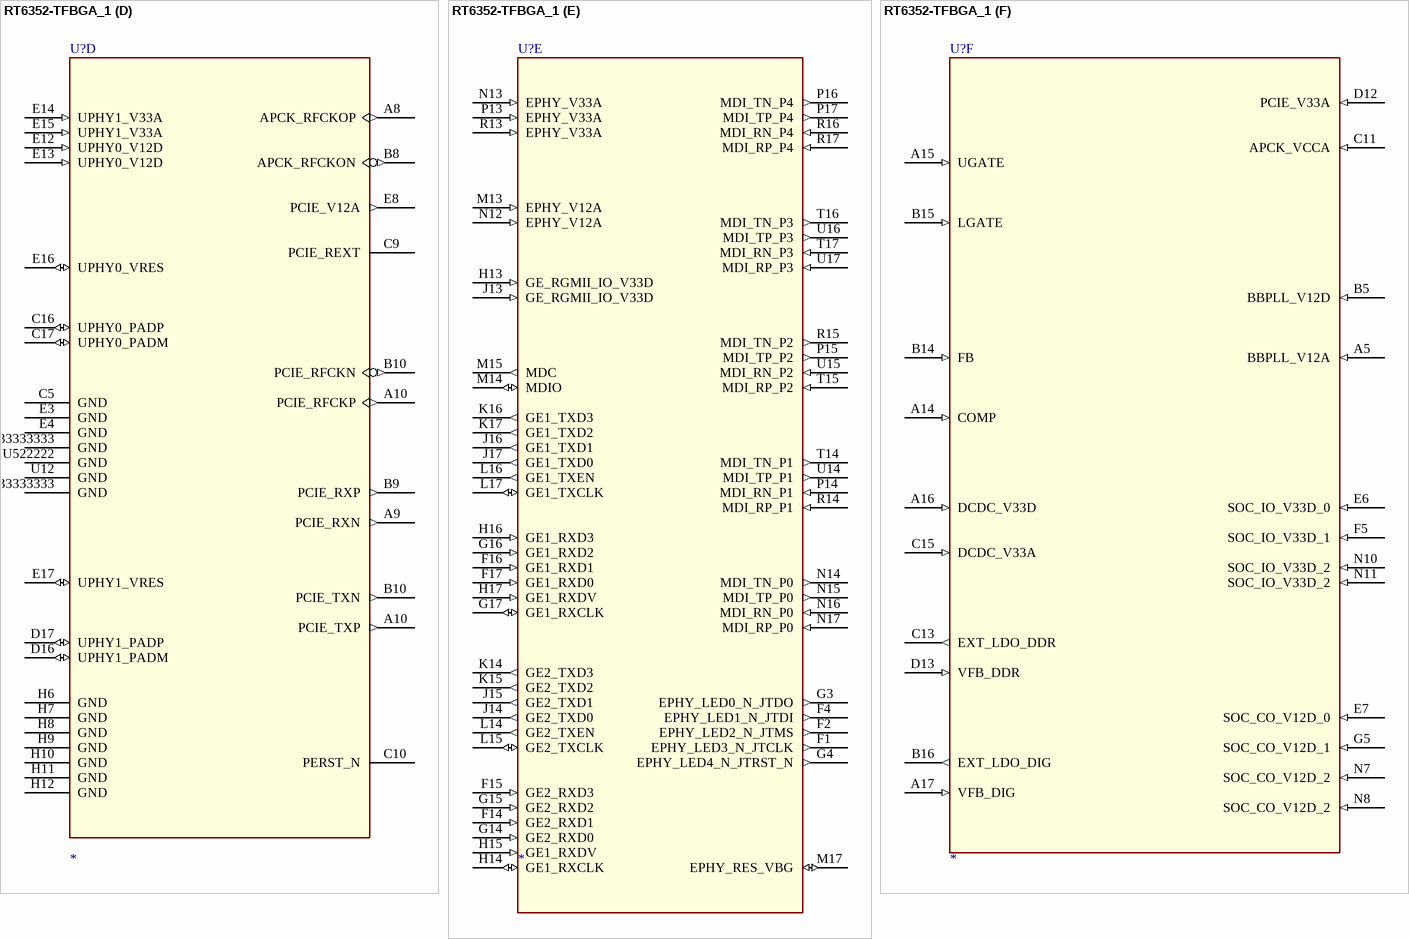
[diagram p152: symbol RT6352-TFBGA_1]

## RT6352-TFBGA_1
designator U?
footprint RT6352/BGA289/P0.65/12X12
part A pins: A1 RF0_PA2_V33P (in), A2 RF0_OUTP (out), A3 PLL_VC_CAP (out), A4 XTAL_XO (out), A6 ANT_TRN (out), B1 RF0_PA2_V33N (in), B2 RF0_OUTN (out), B3 PLL_VX_LDO (out), B4 XTAL_XI (out), B6 ANT_TRNB (out), C1 RF0_PA1_V33A (in), C2 RF1_VX_LDO (out), C3 RF0_VX_LDO (out), C4 XTAL_V12A (out), C6 PA_PE_G0 (out), D1 RF1_PA2_V33P (in), D2 RF1_PA2_V33N (in), D3 RF1_PA1_V33A (in), D4 BG_EXTR (out), D5 BG_V33A (out), D6 PA_PE_G1 (out), E1 RF1_OUTP (out), E2 RF1_OUTN (out), F3 WLED_N (out)
part B pins: F6 GND (power), F7 GND (power), F8 GND (power), F9 GND (power), F10 GND (power), F11 GND (power), F12 GND (power), G1 MD14 / MD15 (io), G2 MD9 / MD14 (io), G6 GND (power), G7 GND (power), G8 GND (power), G9 GND (power), G10 GND (power), G11 GND (power), G12 GND (power), H1 MD12 / MD13 (io), H2 MD11 / MD12 (io), H3 MRAS_N / MA5 (io), H4 MODT / MA4 (io), H5 DDR_IO_V18D/DDR_IO_V25D (in), J1 MD10 / MD11 (io), J2 MD13 / MD10 (io), J3 MCAS_N / MA7 (io), J4 MCS_N / MA6 (io), J5 DDR_IO_V18D/DDR_IO_V25D (in), K1 MD8 / MD9 (io), K2 MD15 / MD8 (io), K3 MA0 / MA8 (io), K4 MA2 / MA9 (io), K5 DDR_IOC_V12D (in), L1 MDQS1 (in), L2 MDQM1 (io), L3 MA6 / MA12 (io), L4 MA4 / MA11 (io), L5 DDR_IOC_V12D (in), M1 MCK_N (io), M2 MCK_P (io), M3 MA8 / MCKE (io), M5 MA11 / MODT (io), N1 MD5 / MD0 (io), N2 MD2 / MD1 (io), N3 MA9 / MA3 (io), N4 DDR_IO_VREF (in), N5 DDR_IO_V18D/DDR_IO_V25D (in), N6 DDR_IO_V18D/DDR_IO_V25D (in), P1 MD0 / MD2 (io), P2 MD7 / MD3 (io), P3 MA12 / MA2 (io), P4 MA7 / MA1 (io), P5 DDR_IO_VREF (in), R1 MD6 /MD4 (io), R2 MD1 / MD5 (io), R3 MA5 / MA0 (io), R4 MA3 / MA10 (io), T1 MD4 / MD6 (io), T2 MD3 / MD7 (io), T3 MA1 / MBA1 (io), T4 MBA0 / MCS_N (io), T5 MWE_N / MCAS_N (io), U1 MDQS0 (io), U2 MDQM0 (io), U3 MA10 / MBA0 (io), U4 MBA1 / MRAS_N (io), U5 MCKE / MWE_N (io)
part C pins: A7 SPI_CS0 (out), B7 SPI_CS1 (out), B17 PORST_N (in), C7 WDT_RST_N (out), C8 SPI_HOLD (out), D7 GPIO0 (io), D8 SPI_WP (out), D9 SPI_MISO (in), D10 SPI_MOSI (out), D11 SPI_CLK (out), J6 GND (power), J7 GND (power), J8 GND (power), J9 GND (power), J10 GND (power), J11 GND (power), J12 GND (power), K6 GND (power), K7 GND (power), K8 GND (power), K9 GND (power), K10 GND (power), K11 GND (power), K12 GND (power), L6 GND (power), L7 GND (power), L8 GND (power), L9 GND (power), L10 GND (power), L11 GND (power), L12 GND (power), M6 GND (power), M7 GND (power), M8 GND (power), M9 GND (power), M10 GND (power), M11 GND (power), M12 GND (power), P6 TXD2 (out), P7 RTS_N (out), P8 ND_D3/SD_D3 (out), P9 ND_D2/SD_D2 (out), P10 ND_D1/SD_D1 (out), P11 DSR_N (io), P12 RXD (io), R6 RXD2 (in), R7 ND_D5/bt_aux (out), R8 ND_CS_N (out), R9 ND_WP/SD_WP (out), R10 ND_D0/SD_D0 (out), R11 DCD_N (io), R12 RIN (io), T6 I2C_SD (out), T7 ND_D6/bt_wact (out), T8 ND_CLE/SD_card_detect, T9 ND_WE_N (out), T10 ND_ALE/SD_CMD (out), T11 TXD (out), T12 CTS_N (io), U6 I2C_SCLK (io), U7 ND_D7/bt_ant (out), U8 ND_D4/bt_stat (out), U9 ND_RE_N (out), U10 ND_RB_N/SD_CLK (out), U11 DTR_N (out)
part D pins: A8 APCK_RFCKOP (out), A9 PCIE_RXN (out), A10 PCIE_RFCKP (out), A10 PCIE_TXP (out), B8 APCK_RFCKON (out), B9 PCIE_RXP (out), B10 PCIE_RFCKN (out), B10 PCIE_TXN (out), C5 GND (power), C9 PCIE_REXT, C10 PERST_N, C16 UPHY0_PADP (io), C17 UPHY0_PADM (io), D16 UPHY1_PADM (io), D17 UPHY1_PADP (io), E3 GND (power), E4 GND (power), E8 PCIE_V12A (out), E12 UPHY0_V12D (in), E13 UPHY0_V12D (in), E14 UPHY1_V33A (in), E15 UPHY1_V33A (in), E16 UPHY0_VRES (io), E17 UPHY1_VRES (io), H6 GND (power), H7 GND (power), H8 GND (power), H9 GND (power), H10 GND (power), H11 GND (power), H12 GND (power), K33333333 GND (power), R17333333333 GND (power), U12 GND (power), U522222 GND (power)
part E pins: F1 EPHY_LED3_N_JTCLK (out), F2 EPHY_LED2_N_JTMS (out), F4 EPHY_LED1_N_JTDI (out), F14 GE2_RXD1 (in), F15 GE2_RXD3 (in), F16 GE1_RXD1 (in), F17 GE1_RXD0 (in), G3 EPHY_LED0_N_JTDO (out), G4 EPHY_LED4_N_JTRST_N (out), G14 GE2_RXD0 (in), G15 GE2_RXD2 (in), G16 GE1_RXD2 (in), G17 GE1_RXCLK (io), H13 GE_RGMII_IO_V33D (in), H14 GE1_RXCLK (io), H15 GE1_RXDV (in), H16 GE1_RXD3 (in), H17 GE1_RXDV (in), J13 GE_RGMII_IO_V33D (in), J14 GE2_TXD0 (out), J15 GE2_TXD1 (out), J16 GE1_TXD1 (out), J17 GE1_TXD0 (out), K14 GE2_TXD3 (out), K15 GE2_TXD2 (out), K16 GE1_TXD3 (out), K17 GE1_TXD2 (out), L14 GE2_TXEN (out), L15 GE2_TXCLK (io), L16 GE1_TXEN (out), L17 GE1_TXCLK (io), M13 EPHY_V12A (in), M14 MDIO (io), M15 MDC (out), M17 EPHY_RES_VBG (io), N12 EPHY_V12A (in), N13 EPHY_V33A (in), N14 MDI_TN_P0 (out), N15 MDI_TP_P0 (out), N16 MDI_RN_P0 (in), N17 MDI_RP_P0 (in), P13 EPHY_V33A (in), P14 MDI_RN_P1 (in), P15 MDI_TP_P2 (out), P16 MDI_TN_P4 (out), P17 MDI_TP_P4 (out), R13 EPHY_V33A (in), R14 MDI_RP_P1 (in), R15 MDI_TN_P2 (out), R16 MDI_RN_P4 (in), R17 MDI_RP_P4 (in), T14 MDI_TN_P1 (out), T15 MDI_RP_P2 (in), T16 MDI_TN_P3 (out), T17 MDI_RN_P3 (in), U14 MDI_TP_P1 (out), U15 MDI_RN_P2 (in), U16 MDI_TP_P3 (out), U17 MDI_RP_P3 (in)
part F pins: A5 BBPLL_V12A (in), A14 COMP (in), A15 UGATE (in), A16 DCDC_V33D (in), A17 VFB_DIG (in), B5 BBPLL_V12D (in), B14 FB (in), B15 LGATE (in), B16 EXT_LDO_DIG (out), C11 APCK_VCCA (in), C13 EXT_LDO_DDR (out), C15 DCDC_V33A (in), D12 PCIE_V33A (in), D13 VFB_DDR (in), E6 SOC_IO_V33D_0 (in), E7 SOC_CO_V12D_0 (in), F5 SOC_IO_V33D_1 (in), G5 SOC_CO_V12D_1 (in), N7 SOC_CO_V12D_2 (in), N8 SOC_CO_V12D_2 (in), N10 SOC_IO_V33D_2 (in), N11 SOC_IO_V33D_2 (in)

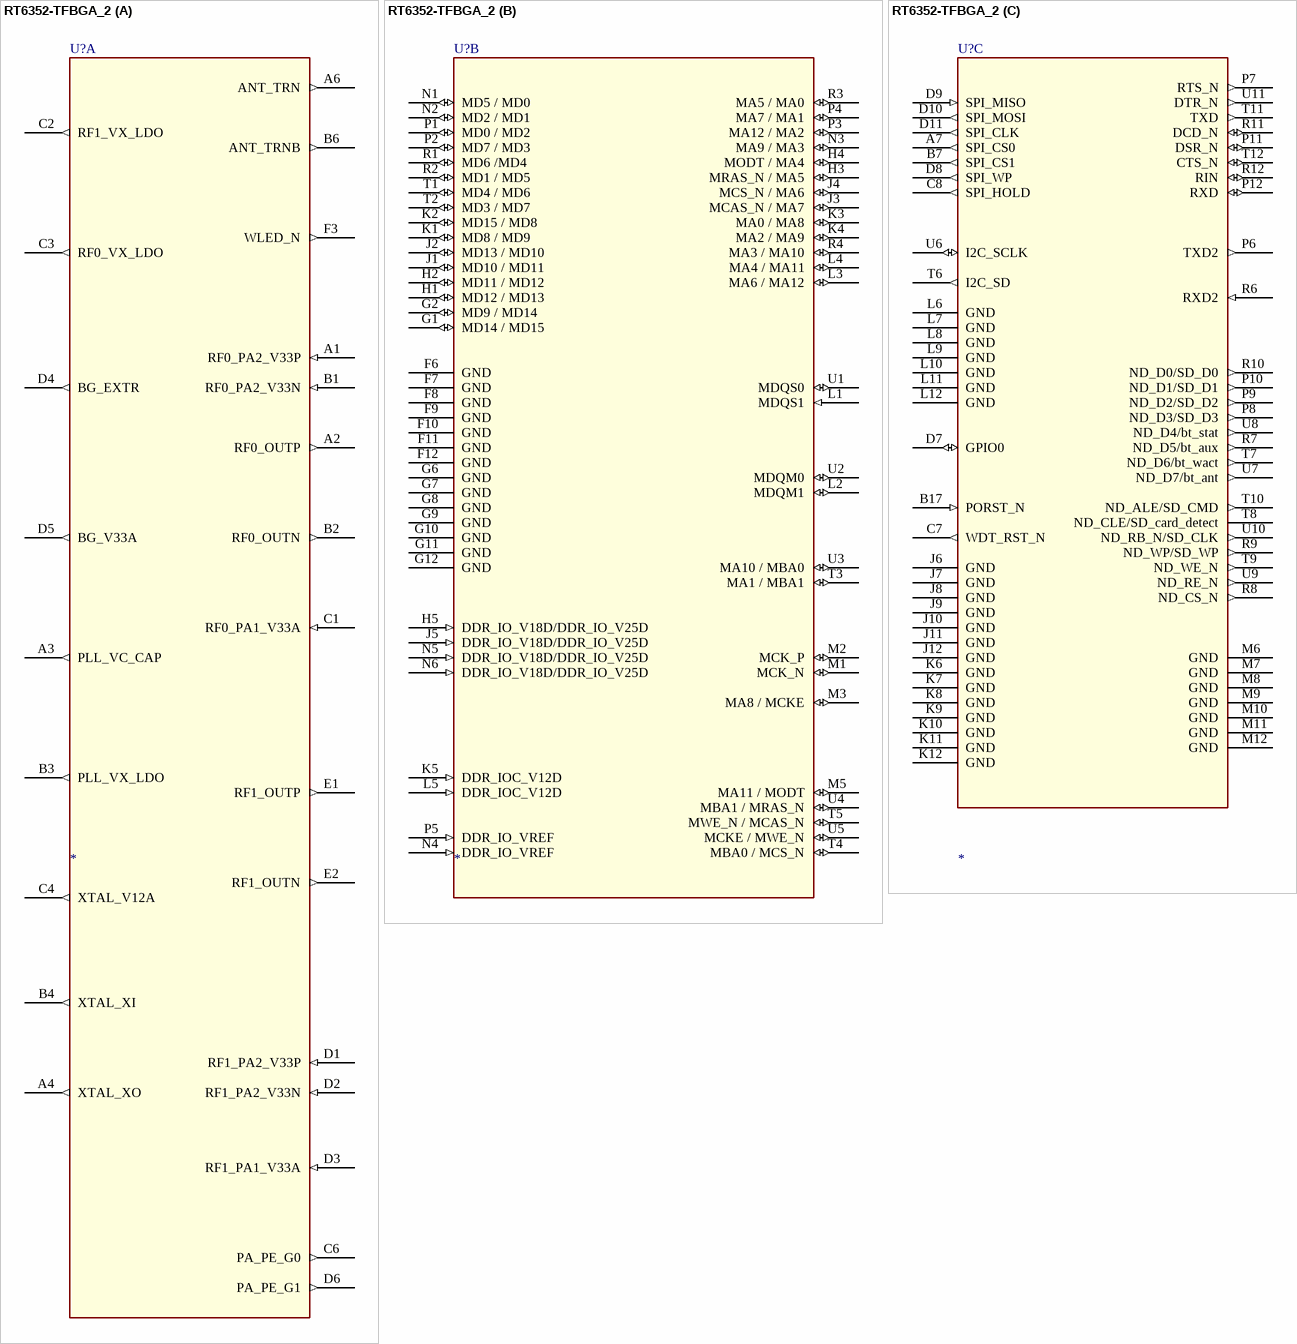
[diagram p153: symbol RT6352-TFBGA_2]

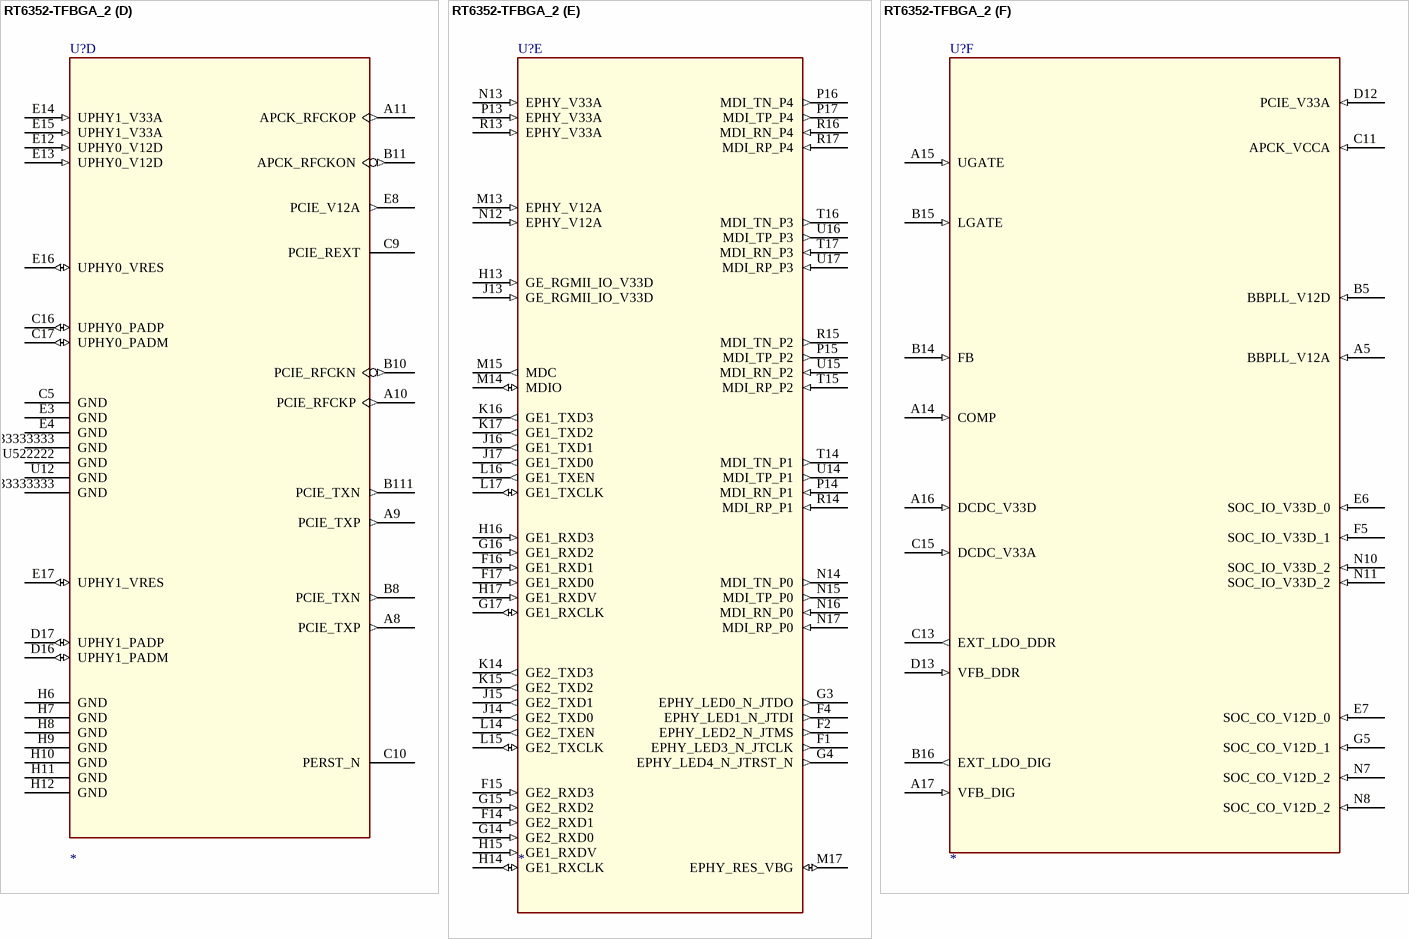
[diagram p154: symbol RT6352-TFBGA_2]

## RT6352-TFBGA_2
designator U?
footprint RT6352/BGA289/P0.65/12X12
part A pins: A1 RF0_PA2_V33P (in), A2 RF0_OUTP (out), A3 PLL_VC_CAP (out), A4 XTAL_XO (out), A6 ANT_TRN (out), B1 RF0_PA2_V33N (in), B2 RF0_OUTN (out), B3 PLL_VX_LDO (out), B4 XTAL_XI (out), B6 ANT_TRNB (out), C1 RF0_PA1_V33A (in), C2 RF1_VX_LDO (out), C3 RF0_VX_LDO (out), C4 XTAL_V12A (out), C6 PA_PE_G0 (out), D1 RF1_PA2_V33P (in), D2 RF1_PA2_V33N (in), D3 RF1_PA1_V33A (in), D4 BG_EXTR (out), D5 BG_V33A (out), D6 PA_PE_G1 (out), E1 RF1_OUTP (out), E2 RF1_OUTN (out), F3 WLED_N (out)
part B pins: F6 GND (power), F7 GND (power), F8 GND (power), F9 GND (power), F10 GND (power), F11 GND (power), F12 GND (power), G1 MD14 / MD15 (io), G2 MD9 / MD14 (io), G6 GND (power), G7 GND (power), G8 GND (power), G9 GND (power), G10 GND (power), G11 GND (power), G12 GND (power), H1 MD12 / MD13 (io), H2 MD11 / MD12 (io), H3 MRAS_N / MA5 (io), H4 MODT / MA4 (io), H5 DDR_IO_V18D/DDR_IO_V25D (in), J1 MD10 / MD11 (io), J2 MD13 / MD10 (io), J3 MCAS_N / MA7 (io), J4 MCS_N / MA6 (io), J5 DDR_IO_V18D/DDR_IO_V25D (in), K1 MD8 / MD9 (io), K2 MD15 / MD8 (io), K3 MA0 / MA8 (io), K4 MA2 / MA9 (io), K5 DDR_IOC_V12D (in), L1 MDQS1 (in), L2 MDQM1 (io), L3 MA6 / MA12 (io), L4 MA4 / MA11 (io), L5 DDR_IOC_V12D (in), M1 MCK_N (io), M2 MCK_P (io), M3 MA8 / MCKE (io), M5 MA11 / MODT (io), N1 MD5 / MD0 (io), N2 MD2 / MD1 (io), N3 MA9 / MA3 (io), N4 DDR_IO_VREF (in), N5 DDR_IO_V18D/DDR_IO_V25D (in), N6 DDR_IO_V18D/DDR_IO_V25D (in), P1 MD0 / MD2 (io), P2 MD7 / MD3 (io), P3 MA12 / MA2 (io), P4 MA7 / MA1 (io), P5 DDR_IO_VREF (in), R1 MD6 /MD4 (io), R2 MD1 / MD5 (io), R3 MA5 / MA0 (io), R4 MA3 / MA10 (io), T1 MD4 / MD6 (io), T2 MD3 / MD7 (io), T3 MA1 / MBA1 (io), T4 MBA0 / MCS_N (io), T5 MWE_N / MCAS_N (io), U1 MDQS0 (io), U2 MDQM0 (io), U3 MA10 / MBA0 (io), U4 MBA1 / MRAS_N (io), U5 MCKE / MWE_N (io)
part C pins: A7 SPI_CS0 (out), B7 SPI_CS1 (out), B17 PORST_N (in), C7 WDT_RST_N (out), C8 SPI_HOLD (out), D7 GPIO0 (io), D8 SPI_WP (out), D9 SPI_MISO (in), D10 SPI_MOSI (out), D11 SPI_CLK (out), J6 GND (power), J7 GND (power), J8 GND (power), J9 GND (power), J10 GND (power), J11 GND (power), J12 GND (power), K6 GND (power), K7 GND (power), K8 GND (power), K9 GND (power), K10 GND (power), K11 GND (power), K12 GND (power), L6 GND (power), L7 GND (power), L8 GND (power), L9 GND (power), L10 GND (power), L11 GND (power), L12 GND (power), M6 GND (power), M7 GND (power), M8 GND (power), M9 GND (power), M10 GND (power), M11 GND (power), M12 GND (power), P6 TXD2 (out), P7 RTS_N (out), P8 ND_D3/SD_D3 (out), P9 ND_D2/SD_D2 (out), P10 ND_D1/SD_D1 (out), P11 DSR_N (io), P12 RXD (io), R6 RXD2 (in), R7 ND_D5/bt_aux (out), R8 ND_CS_N (out), R9 ND_WP/SD_WP (out), R10 ND_D0/SD_D0 (out), R11 DCD_N (io), R12 RIN (io), T6 I2C_SD (out), T7 ND_D6/bt_wact (out), T8 ND_CLE/SD_card_detect, T9 ND_WE_N (out), T10 ND_ALE/SD_CMD (out), T11 TXD (out), T12 CTS_N (io), U6 I2C_SCLK (io), U7 ND_D7/bt_ant (out), U8 ND_D4/bt_stat (out), U9 ND_RE_N (out), U10 ND_RB_N/SD_CLK (out), U11 DTR_N (out)
part D pins: A8 PCIE_TXP (out), A9 PCIE_TXP (out), A10 PCIE_RFCKP (out), A11 APCK_RFCKOP (out), B8 PCIE_TXN (out), B10 PCIE_RFCKN (out), B11 APCK_RFCKON (out), B111 PCIE_TXN (out), C5 GND (power), C9 PCIE_REXT, C10 PERST_N, C16 UPHY0_PADP (io), C17 UPHY0_PADM (io), D16 UPHY1_PADM (io), D17 UPHY1_PADP (io), E3 GND (power), E4 GND (power), E8 PCIE_V12A (out), E12 UPHY0_V12D (in), E13 UPHY0_V12D (in), E14 UPHY1_V33A (in), E15 UPHY1_V33A (in), E16 UPHY0_VRES (io), E17 UPHY1_VRES (io), H6 GND (power), H7 GND (power), H8 GND (power), H9 GND (power), H10 GND (power), H11 GND (power), H12 GND (power), K33333333 GND (power), R17333333333 GND (power), U12 GND (power), U522222 GND (power)
part E pins: F1 EPHY_LED3_N_JTCLK (out), F2 EPHY_LED2_N_JTMS (out), F4 EPHY_LED1_N_JTDI (out), F14 GE2_RXD1 (in), F15 GE2_RXD3 (in), F16 GE1_RXD1 (in), F17 GE1_RXD0 (in), G3 EPHY_LED0_N_JTDO (out), G4 EPHY_LED4_N_JTRST_N (out), G14 GE2_RXD0 (in), G15 GE2_RXD2 (in), G16 GE1_RXD2 (in), G17 GE1_RXCLK (io), H13 GE_RGMII_IO_V33D (in), H14 GE1_RXCLK (io), H15 GE1_RXDV (in), H16 GE1_RXD3 (in), H17 GE1_RXDV (in), J13 GE_RGMII_IO_V33D (in), J14 GE2_TXD0 (out), J15 GE2_TXD1 (out), J16 GE1_TXD1 (out), J17 GE1_TXD0 (out), K14 GE2_TXD3 (out), K15 GE2_TXD2 (out), K16 GE1_TXD3 (out), K17 GE1_TXD2 (out), L14 GE2_TXEN (out), L15 GE2_TXCLK (io), L16 GE1_TXEN (out), L17 GE1_TXCLK (io), M13 EPHY_V12A (in), M14 MDIO (io), M15 MDC (out), M17 EPHY_RES_VBG (io), N12 EPHY_V12A (in), N13 EPHY_V33A (in), N14 MDI_TN_P0 (out), N15 MDI_TP_P0 (out), N16 MDI_RN_P0 (in), N17 MDI_RP_P0 (in), P13 EPHY_V33A (in), P14 MDI_RN_P1 (in), P15 MDI_TP_P2 (out), P16 MDI_TN_P4 (out), P17 MDI_TP_P4 (out), R13 EPHY_V33A (in), R14 MDI_RP_P1 (in), R15 MDI_TN_P2 (out), R16 MDI_RN_P4 (in), R17 MDI_RP_P4 (in), T14 MDI_TN_P1 (out), T15 MDI_RP_P2 (in), T16 MDI_TN_P3 (out), T17 MDI_RN_P3 (in), U14 MDI_TP_P1 (out), U15 MDI_RN_P2 (in), U16 MDI_TP_P3 (out), U17 MDI_RP_P3 (in)
part F pins: A5 BBPLL_V12A (in), A14 COMP (in), A15 UGATE (in), A16 DCDC_V33D (in), A17 VFB_DIG (in), B5 BBPLL_V12D (in), B14 FB (in), B15 LGATE (in), B16 EXT_LDO_DIG (out), C11 APCK_VCCA (in), C13 EXT_LDO_DDR (out), C15 DCDC_V33A (in), D12 PCIE_V33A (in), D13 VFB_DDR (in), E6 SOC_IO_V33D_0 (in), E7 SOC_CO_V12D_0 (in), F5 SOC_IO_V33D_1 (in), G5 SOC_CO_V12D_1 (in), N7 SOC_CO_V12D_2 (in), N8 SOC_CO_V12D_2 (in), N10 SOC_IO_V33D_2 (in), N11 SOC_IO_V33D_2 (in)

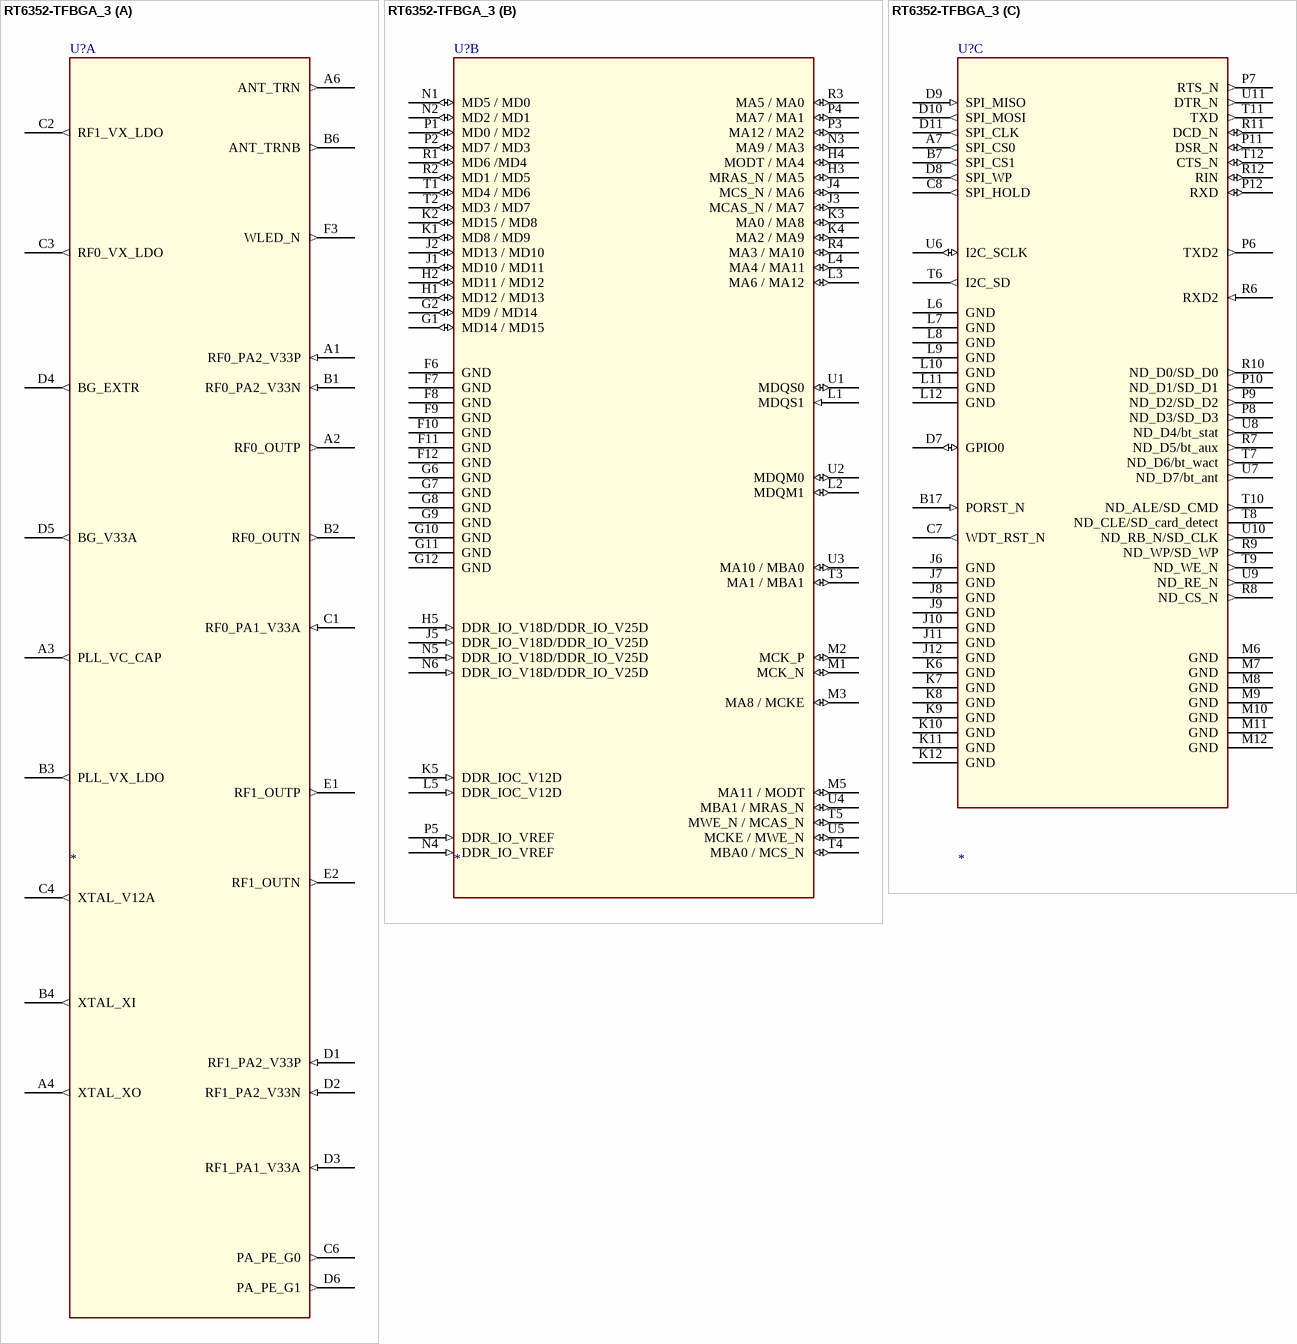
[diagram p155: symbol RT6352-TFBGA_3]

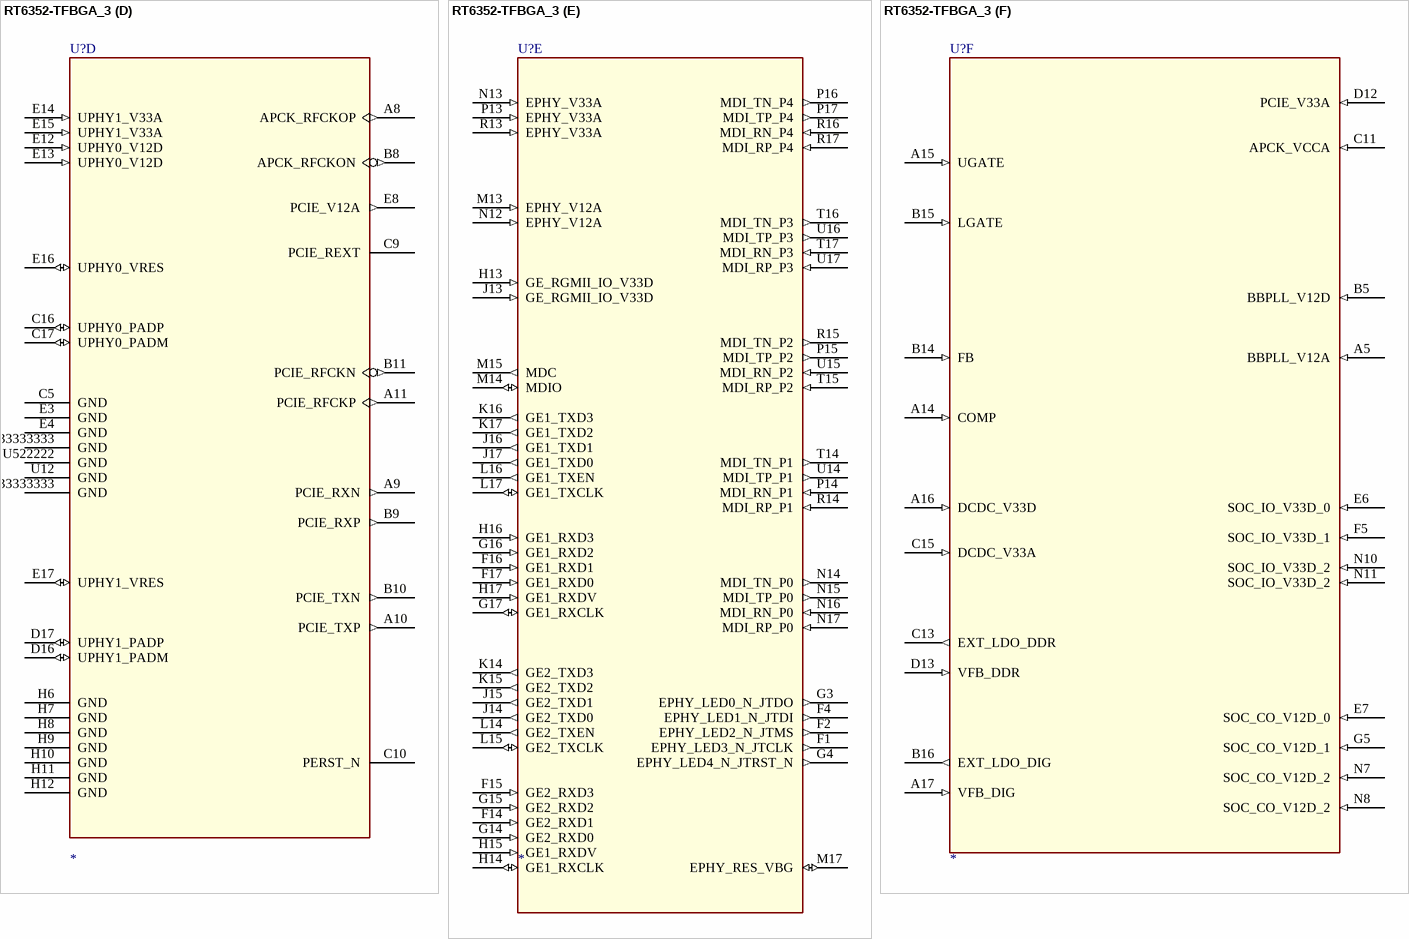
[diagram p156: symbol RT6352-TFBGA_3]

## RT6352-TFBGA_3
designator U?
footprint RT6352/BGA289/P0.65/12X12
part A pins: A1 RF0_PA2_V33P (in), A2 RF0_OUTP (out), A3 PLL_VC_CAP (out), A4 XTAL_XO (out), A6 ANT_TRN (out), B1 RF0_PA2_V33N (in), B2 RF0_OUTN (out), B3 PLL_VX_LDO (out), B4 XTAL_XI (out), B6 ANT_TRNB (out), C1 RF0_PA1_V33A (in), C2 RF1_VX_LDO (out), C3 RF0_VX_LDO (out), C4 XTAL_V12A (out), C6 PA_PE_G0 (out), D1 RF1_PA2_V33P (in), D2 RF1_PA2_V33N (in), D3 RF1_PA1_V33A (in), D4 BG_EXTR (out), D5 BG_V33A (out), D6 PA_PE_G1 (out), E1 RF1_OUTP (out), E2 RF1_OUTN (out), F3 WLED_N (out)
part B pins: F6 GND (power), F7 GND (power), F8 GND (power), F9 GND (power), F10 GND (power), F11 GND (power), F12 GND (power), G1 MD14 / MD15 (io), G2 MD9 / MD14 (io), G6 GND (power), G7 GND (power), G8 GND (power), G9 GND (power), G10 GND (power), G11 GND (power), G12 GND (power), H1 MD12 / MD13 (io), H2 MD11 / MD12 (io), H3 MRAS_N / MA5 (io), H4 MODT / MA4 (io), H5 DDR_IO_V18D/DDR_IO_V25D (in), J1 MD10 / MD11 (io), J2 MD13 / MD10 (io), J3 MCAS_N / MA7 (io), J4 MCS_N / MA6 (io), J5 DDR_IO_V18D/DDR_IO_V25D (in), K1 MD8 / MD9 (io), K2 MD15 / MD8 (io), K3 MA0 / MA8 (io), K4 MA2 / MA9 (io), K5 DDR_IOC_V12D (in), L1 MDQS1 (in), L2 MDQM1 (io), L3 MA6 / MA12 (io), L4 MA4 / MA11 (io), L5 DDR_IOC_V12D (in), M1 MCK_N (io), M2 MCK_P (io), M3 MA8 / MCKE (io), M5 MA11 / MODT (io), N1 MD5 / MD0 (io), N2 MD2 / MD1 (io), N3 MA9 / MA3 (io), N4 DDR_IO_VREF (in), N5 DDR_IO_V18D/DDR_IO_V25D (in), N6 DDR_IO_V18D/DDR_IO_V25D (in), P1 MD0 / MD2 (io), P2 MD7 / MD3 (io), P3 MA12 / MA2 (io), P4 MA7 / MA1 (io), P5 DDR_IO_VREF (in), R1 MD6 /MD4 (io), R2 MD1 / MD5 (io), R3 MA5 / MA0 (io), R4 MA3 / MA10 (io), T1 MD4 / MD6 (io), T2 MD3 / MD7 (io), T3 MA1 / MBA1 (io), T4 MBA0 / MCS_N (io), T5 MWE_N / MCAS_N (io), U1 MDQS0 (io), U2 MDQM0 (io), U3 MA10 / MBA0 (io), U4 MBA1 / MRAS_N (io), U5 MCKE / MWE_N (io)
part C pins: A7 SPI_CS0 (out), B7 SPI_CS1 (out), B17 PORST_N (in), C7 WDT_RST_N (out), C8 SPI_HOLD (out), D7 GPIO0 (io), D8 SPI_WP (out), D9 SPI_MISO (in), D10 SPI_MOSI (out), D11 SPI_CLK (out), J6 GND (power), J7 GND (power), J8 GND (power), J9 GND (power), J10 GND (power), J11 GND (power), J12 GND (power), K6 GND (power), K7 GND (power), K8 GND (power), K9 GND (power), K10 GND (power), K11 GND (power), K12 GND (power), L6 GND (power), L7 GND (power), L8 GND (power), L9 GND (power), L10 GND (power), L11 GND (power), L12 GND (power), M6 GND (power), M7 GND (power), M8 GND (power), M9 GND (power), M10 GND (power), M11 GND (power), M12 GND (power), P6 TXD2 (out), P7 RTS_N (out), P8 ND_D3/SD_D3 (out), P9 ND_D2/SD_D2 (out), P10 ND_D1/SD_D1 (out), P11 DSR_N (io), P12 RXD (io), R6 RXD2 (in), R7 ND_D5/bt_aux (out), R8 ND_CS_N (out), R9 ND_WP/SD_WP (out), R10 ND_D0/SD_D0 (out), R11 DCD_N (io), R12 RIN (io), T6 I2C_SD (out), T7 ND_D6/bt_wact (out), T8 ND_CLE/SD_card_detect, T9 ND_WE_N (out), T10 ND_ALE/SD_CMD (out), T11 TXD (out), T12 CTS_N (io), U6 I2C_SCLK (io), U7 ND_D7/bt_ant (out), U8 ND_D4/bt_stat (out), U9 ND_RE_N (out), U10 ND_RB_N/SD_CLK (out), U11 DTR_N (out)
part D pins: A8 APCK_RFCKOP (out), A9 PCIE_RXN (out), A10 PCIE_TXP (out), A11 PCIE_RFCKP (out), B8 APCK_RFCKON (out), B9 PCIE_RXP (out), B10 PCIE_TXN (out), B11 PCIE_RFCKN (out), C5 GND (power), C9 PCIE_REXT, C10 PERST_N, C16 UPHY0_PADP (io), C17 UPHY0_PADM (io), D16 UPHY1_PADM (io), D17 UPHY1_PADP (io), E3 GND (power), E4 GND (power), E8 PCIE_V12A (out), E12 UPHY0_V12D (in), E13 UPHY0_V12D (in), E14 UPHY1_V33A (in), E15 UPHY1_V33A (in), E16 UPHY0_VRES (io), E17 UPHY1_VRES (io), H6 GND (power), H7 GND (power), H8 GND (power), H9 GND (power), H10 GND (power), H11 GND (power), H12 GND (power), K33333333 GND (power), R17333333333 GND (power), U12 GND (power), U522222 GND (power)
part E pins: F1 EPHY_LED3_N_JTCLK (out), F2 EPHY_LED2_N_JTMS (out), F4 EPHY_LED1_N_JTDI (out), F14 GE2_RXD1 (in), F15 GE2_RXD3 (in), F16 GE1_RXD1 (in), F17 GE1_RXD0 (in), G3 EPHY_LED0_N_JTDO (out), G4 EPHY_LED4_N_JTRST_N (out), G14 GE2_RXD0 (in), G15 GE2_RXD2 (in), G16 GE1_RXD2 (in), G17 GE1_RXCLK (io), H13 GE_RGMII_IO_V33D (in), H14 GE1_RXCLK (io), H15 GE1_RXDV (in), H16 GE1_RXD3 (in), H17 GE1_RXDV (in), J13 GE_RGMII_IO_V33D (in), J14 GE2_TXD0 (out), J15 GE2_TXD1 (out), J16 GE1_TXD1 (out), J17 GE1_TXD0 (out), K14 GE2_TXD3 (out), K15 GE2_TXD2 (out), K16 GE1_TXD3 (out), K17 GE1_TXD2 (out), L14 GE2_TXEN (out), L15 GE2_TXCLK (io), L16 GE1_TXEN (out), L17 GE1_TXCLK (io), M13 EPHY_V12A (in), M14 MDIO (io), M15 MDC (out), M17 EPHY_RES_VBG (io), N12 EPHY_V12A (in), N13 EPHY_V33A (in), N14 MDI_TN_P0 (out), N15 MDI_TP_P0 (out), N16 MDI_RN_P0 (in), N17 MDI_RP_P0 (in), P13 EPHY_V33A (in), P14 MDI_RN_P1 (in), P15 MDI_TP_P2 (out), P16 MDI_TN_P4 (out), P17 MDI_TP_P4 (out), R13 EPHY_V33A (in), R14 MDI_RP_P1 (in), R15 MDI_TN_P2 (out), R16 MDI_RN_P4 (in), R17 MDI_RP_P4 (in), T14 MDI_TN_P1 (out), T15 MDI_RP_P2 (in), T16 MDI_TN_P3 (out), T17 MDI_RN_P3 (in), U14 MDI_TP_P1 (out), U15 MDI_RN_P2 (in), U16 MDI_TP_P3 (out), U17 MDI_RP_P3 (in)
part F pins: A5 BBPLL_V12A (in), A14 COMP (in), A15 UGATE (in), A16 DCDC_V33D (in), A17 VFB_DIG (in), B5 BBPLL_V12D (in), B14 FB (in), B15 LGATE (in), B16 EXT_LDO_DIG (out), C11 APCK_VCCA (in), C13 EXT_LDO_DDR (out), C15 DCDC_V33A (in), D12 PCIE_V33A (in), D13 VFB_DDR (in), E6 SOC_IO_V33D_0 (in), E7 SOC_CO_V12D_0 (in), F5 SOC_IO_V33D_1 (in), G5 SOC_CO_V12D_1 (in), N7 SOC_CO_V12D_2 (in), N8 SOC_CO_V12D_2 (in), N10 SOC_IO_V33D_2 (in), N11 SOC_IO_V33D_2 (in)

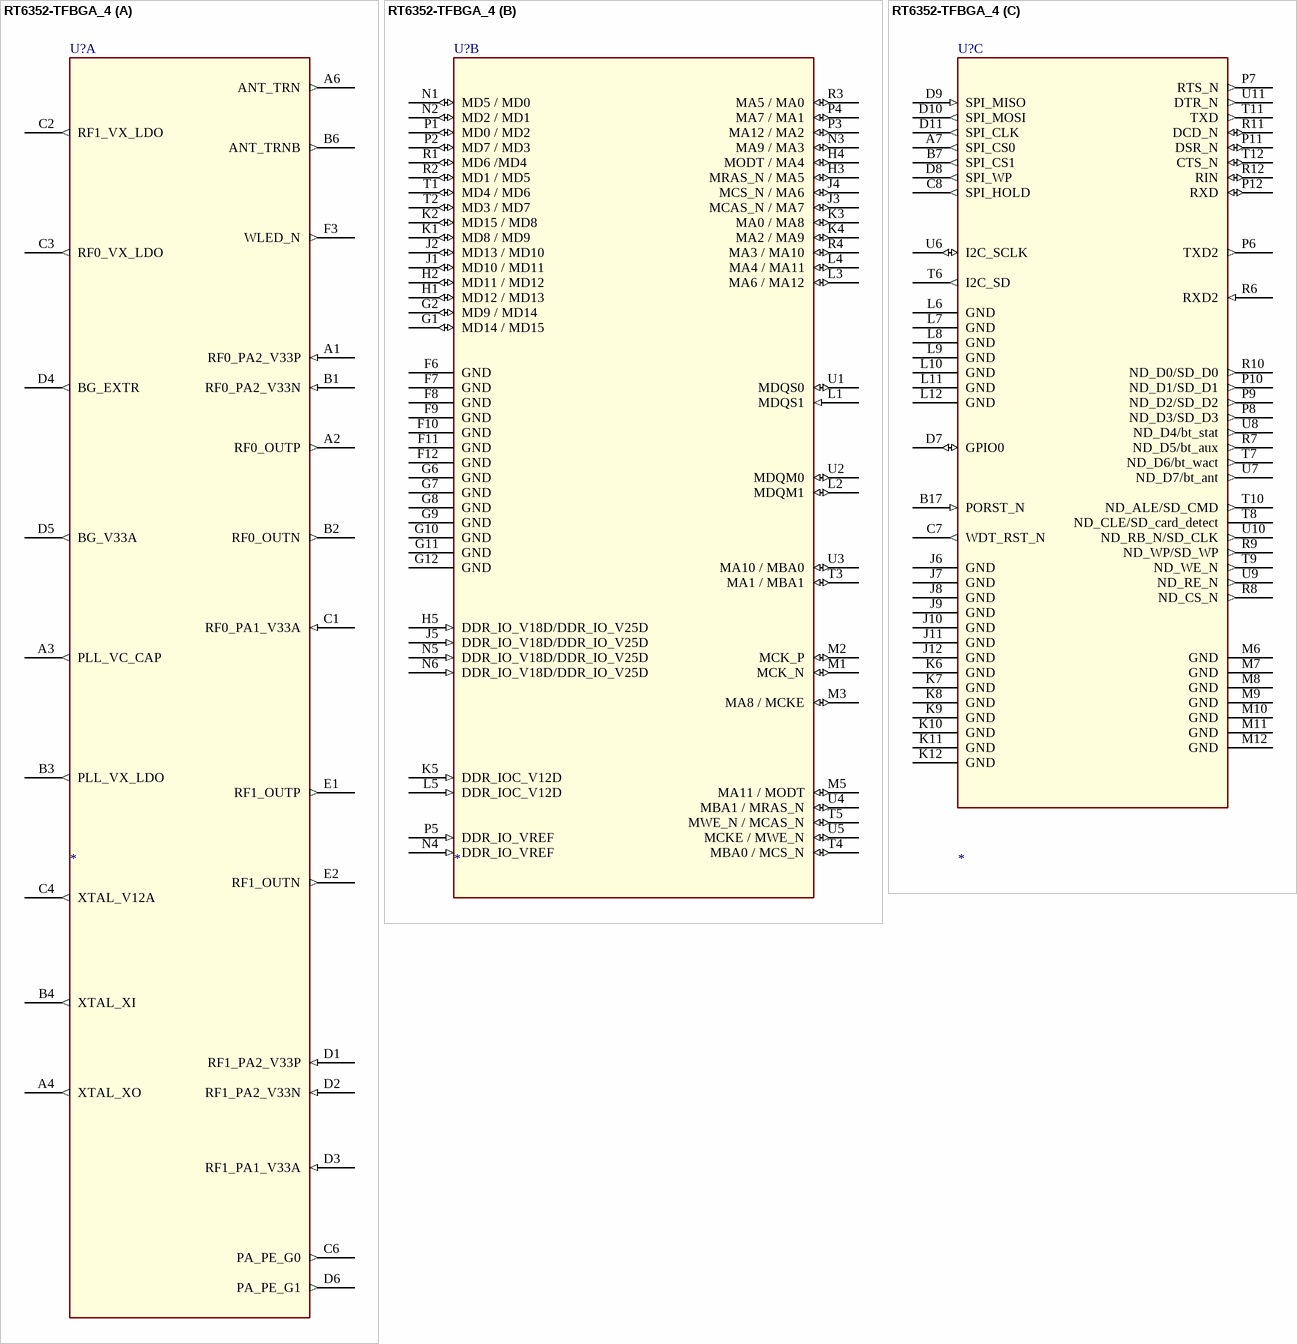
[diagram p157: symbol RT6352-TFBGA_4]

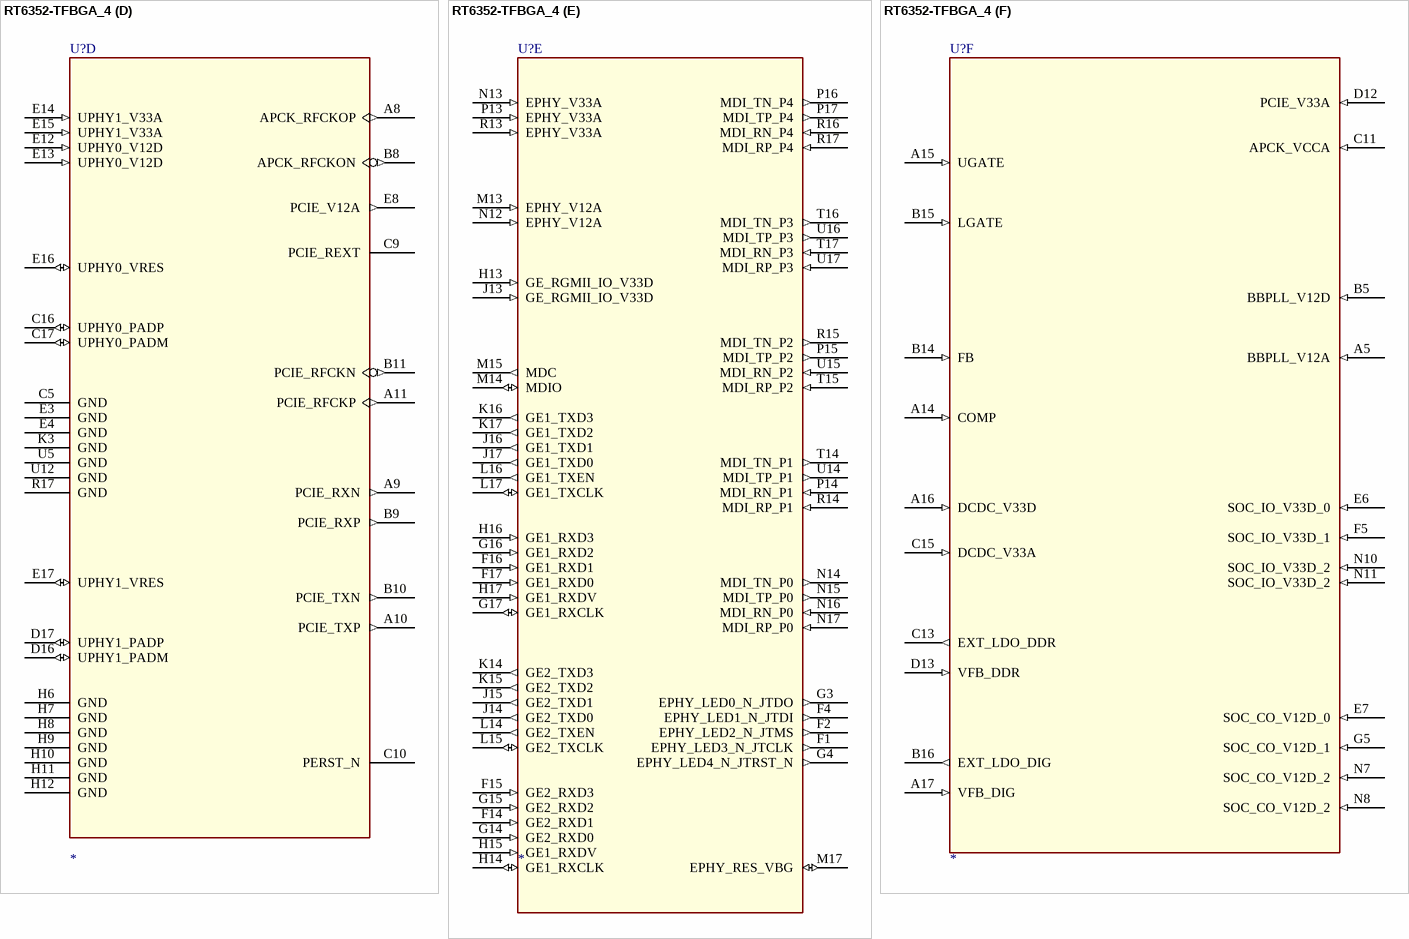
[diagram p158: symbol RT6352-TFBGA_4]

## RT6352-TFBGA_4
designator U?
footprint RT6352/BGA289/P0.65/12X12
part A pins: A1 RF0_PA2_V33P (in), A2 RF0_OUTP (out), A3 PLL_VC_CAP (out), A4 XTAL_XO (out), A6 ANT_TRN (out), B1 RF0_PA2_V33N (in), B2 RF0_OUTN (out), B3 PLL_VX_LDO (out), B4 XTAL_XI (out), B6 ANT_TRNB (out), C1 RF0_PA1_V33A (in), C2 RF1_VX_LDO (out), C3 RF0_VX_LDO (out), C4 XTAL_V12A (out), C6 PA_PE_G0 (out), D1 RF1_PA2_V33P (in), D2 RF1_PA2_V33N (in), D3 RF1_PA1_V33A (in), D4 BG_EXTR (out), D5 BG_V33A (out), D6 PA_PE_G1 (out), E1 RF1_OUTP (out), E2 RF1_OUTN (out), F3 WLED_N (out)
part B pins: F6 GND (power), F7 GND (power), F8 GND (power), F9 GND (power), F10 GND (power), F11 GND (power), F12 GND (power), G1 MD14 / MD15 (io), G2 MD9 / MD14 (io), G6 GND (power), G7 GND (power), G8 GND (power), G9 GND (power), G10 GND (power), G11 GND (power), G12 GND (power), H1 MD12 / MD13 (io), H2 MD11 / MD12 (io), H3 MRAS_N / MA5 (io), H4 MODT / MA4 (io), H5 DDR_IO_V18D/DDR_IO_V25D (in), J1 MD10 / MD11 (io), J2 MD13 / MD10 (io), J3 MCAS_N / MA7 (io), J4 MCS_N / MA6 (io), J5 DDR_IO_V18D/DDR_IO_V25D (in), K1 MD8 / MD9 (io), K2 MD15 / MD8 (io), K3 MA0 / MA8 (io), K4 MA2 / MA9 (io), K5 DDR_IOC_V12D (in), L1 MDQS1 (in), L2 MDQM1 (io), L3 MA6 / MA12 (io), L4 MA4 / MA11 (io), L5 DDR_IOC_V12D (in), M1 MCK_N (io), M2 MCK_P (io), M3 MA8 / MCKE (io), M5 MA11 / MODT (io), N1 MD5 / MD0 (io), N2 MD2 / MD1 (io), N3 MA9 / MA3 (io), N4 DDR_IO_VREF (in), N5 DDR_IO_V18D/DDR_IO_V25D (in), N6 DDR_IO_V18D/DDR_IO_V25D (in), P1 MD0 / MD2 (io), P2 MD7 / MD3 (io), P3 MA12 / MA2 (io), P4 MA7 / MA1 (io), P5 DDR_IO_VREF (in), R1 MD6 /MD4 (io), R2 MD1 / MD5 (io), R3 MA5 / MA0 (io), R4 MA3 / MA10 (io), T1 MD4 / MD6 (io), T2 MD3 / MD7 (io), T3 MA1 / MBA1 (io), T4 MBA0 / MCS_N (io), T5 MWE_N / MCAS_N (io), U1 MDQS0 (io), U2 MDQM0 (io), U3 MA10 / MBA0 (io), U4 MBA1 / MRAS_N (io), U5 MCKE / MWE_N (io)
part C pins: A7 SPI_CS0 (out), B7 SPI_CS1 (out), B17 PORST_N (in), C7 WDT_RST_N (out), C8 SPI_HOLD (out), D7 GPIO0 (io), D8 SPI_WP (out), D9 SPI_MISO (in), D10 SPI_MOSI (out), D11 SPI_CLK (out), J6 GND (power), J7 GND (power), J8 GND (power), J9 GND (power), J10 GND (power), J11 GND (power), J12 GND (power), K6 GND (power), K7 GND (power), K8 GND (power), K9 GND (power), K10 GND (power), K11 GND (power), K12 GND (power), L6 GND (power), L7 GND (power), L8 GND (power), L9 GND (power), L10 GND (power), L11 GND (power), L12 GND (power), M6 GND (power), M7 GND (power), M8 GND (power), M9 GND (power), M10 GND (power), M11 GND (power), M12 GND (power), P6 TXD2 (out), P7 RTS_N (out), P8 ND_D3/SD_D3 (out), P9 ND_D2/SD_D2 (out), P10 ND_D1/SD_D1 (out), P11 DSR_N (io), P12 RXD (io), R6 RXD2 (in), R7 ND_D5/bt_aux (out), R8 ND_CS_N (out), R9 ND_WP/SD_WP (out), R10 ND_D0/SD_D0 (out), R11 DCD_N (io), R12 RIN (io), T6 I2C_SD (out), T7 ND_D6/bt_wact (out), T8 ND_CLE/SD_card_detect, T9 ND_WE_N (out), T10 ND_ALE/SD_CMD (out), T11 TXD (out), T12 CTS_N (io), U6 I2C_SCLK (io), U7 ND_D7/bt_ant (out), U8 ND_D4/bt_stat (out), U9 ND_RE_N (out), U10 ND_RB_N/SD_CLK (out), U11 DTR_N (out)
part D pins: A8 APCK_RFCKOP (out), A9 PCIE_RXN (out), A10 PCIE_TXP (out), A11 PCIE_RFCKP (out), B8 APCK_RFCKON (out), B9 PCIE_RXP (out), B10 PCIE_TXN (out), B11 PCIE_RFCKN (out), C5 GND (power), C9 PCIE_REXT, C10 PERST_N, C16 UPHY0_PADP (io), C17 UPHY0_PADM (io), D16 UPHY1_PADM (io), D17 UPHY1_PADP (io), E3 GND (power), E4 GND (power), E8 PCIE_V12A (out), E12 UPHY0_V12D (in), E13 UPHY0_V12D (in), E14 UPHY1_V33A (in), E15 UPHY1_V33A (in), E16 UPHY0_VRES (io), E17 UPHY1_VRES (io), H6 GND (power), H7 GND (power), H8 GND (power), H9 GND (power), H10 GND (power), H11 GND (power), H12 GND (power), K3 GND (power), R17 GND (power), U5 GND (power), U12 GND (power)
part E pins: F1 EPHY_LED3_N_JTCLK (out), F2 EPHY_LED2_N_JTMS (out), F4 EPHY_LED1_N_JTDI (out), F14 GE2_RXD1 (in), F15 GE2_RXD3 (in), F16 GE1_RXD1 (in), F17 GE1_RXD0 (in), G3 EPHY_LED0_N_JTDO (out), G4 EPHY_LED4_N_JTRST_N (out), G14 GE2_RXD0 (in), G15 GE2_RXD2 (in), G16 GE1_RXD2 (in), G17 GE1_RXCLK (io), H13 GE_RGMII_IO_V33D (in), H14 GE1_RXCLK (io), H15 GE1_RXDV (in), H16 GE1_RXD3 (in), H17 GE1_RXDV (in), J13 GE_RGMII_IO_V33D (in), J14 GE2_TXD0 (out), J15 GE2_TXD1 (out), J16 GE1_TXD1 (out), J17 GE1_TXD0 (out), K14 GE2_TXD3 (out), K15 GE2_TXD2 (out), K16 GE1_TXD3 (out), K17 GE1_TXD2 (out), L14 GE2_TXEN (out), L15 GE2_TXCLK (io), L16 GE1_TXEN (out), L17 GE1_TXCLK (io), M13 EPHY_V12A (in), M14 MDIO (io), M15 MDC (out), M17 EPHY_RES_VBG (io), N12 EPHY_V12A (in), N13 EPHY_V33A (in), N14 MDI_TN_P0 (out), N15 MDI_TP_P0 (out), N16 MDI_RN_P0 (in), N17 MDI_RP_P0 (in), P13 EPHY_V33A (in), P14 MDI_RN_P1 (in), P15 MDI_TP_P2 (out), P16 MDI_TN_P4 (out), P17 MDI_TP_P4 (out), R13 EPHY_V33A (in), R14 MDI_RP_P1 (in), R15 MDI_TN_P2 (out), R16 MDI_RN_P4 (in), R17 MDI_RP_P4 (in), T14 MDI_TN_P1 (out), T15 MDI_RP_P2 (in), T16 MDI_TN_P3 (out), T17 MDI_RN_P3 (in), U14 MDI_TP_P1 (out), U15 MDI_RN_P2 (in), U16 MDI_TP_P3 (out), U17 MDI_RP_P3 (in)
part F pins: A5 BBPLL_V12A (in), A14 COMP (in), A15 UGATE (in), A16 DCDC_V33D (in), A17 VFB_DIG (in), B5 BBPLL_V12D (in), B14 FB (in), B15 LGATE (in), B16 EXT_LDO_DIG (out), C11 APCK_VCCA (in), C13 EXT_LDO_DDR (out), C15 DCDC_V33A (in), D12 PCIE_V33A (in), D13 VFB_DDR (in), E6 SOC_IO_V33D_0 (in), E7 SOC_CO_V12D_0 (in), F5 SOC_IO_V33D_1 (in), G5 SOC_CO_V12D_1 (in), N7 SOC_CO_V12D_2 (in), N8 SOC_CO_V12D_2 (in), N10 SOC_IO_V33D_2 (in), N11 SOC_IO_V33D_2 (in)

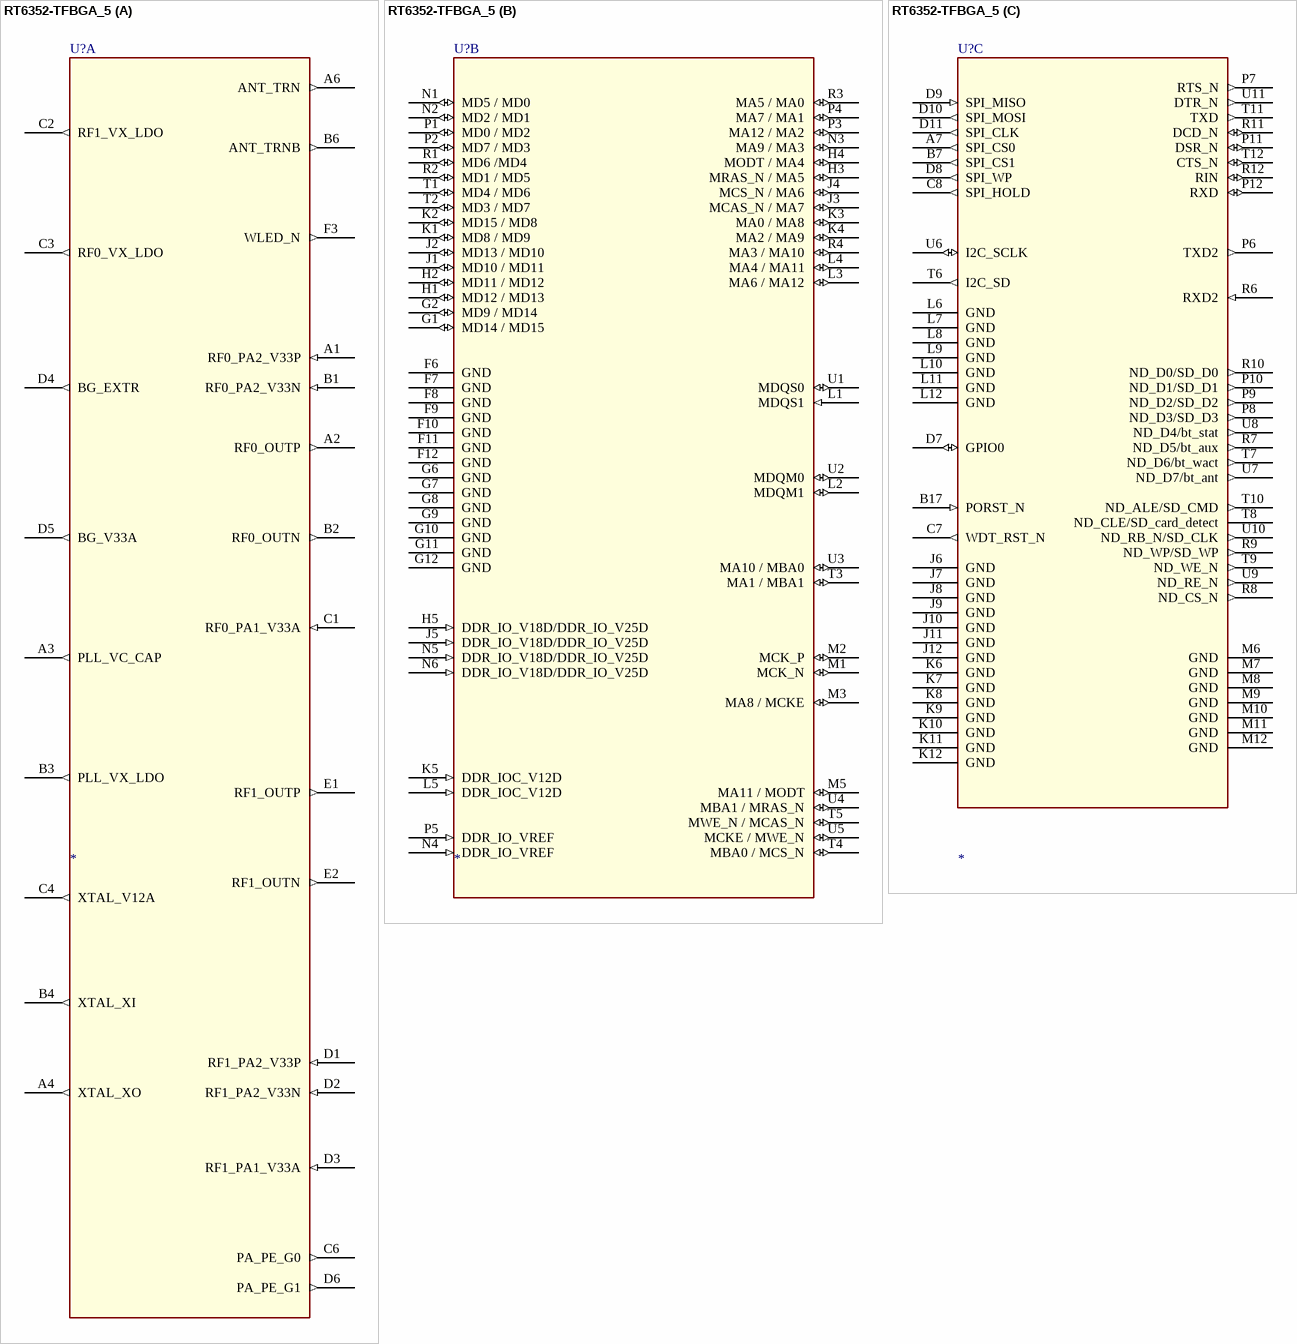
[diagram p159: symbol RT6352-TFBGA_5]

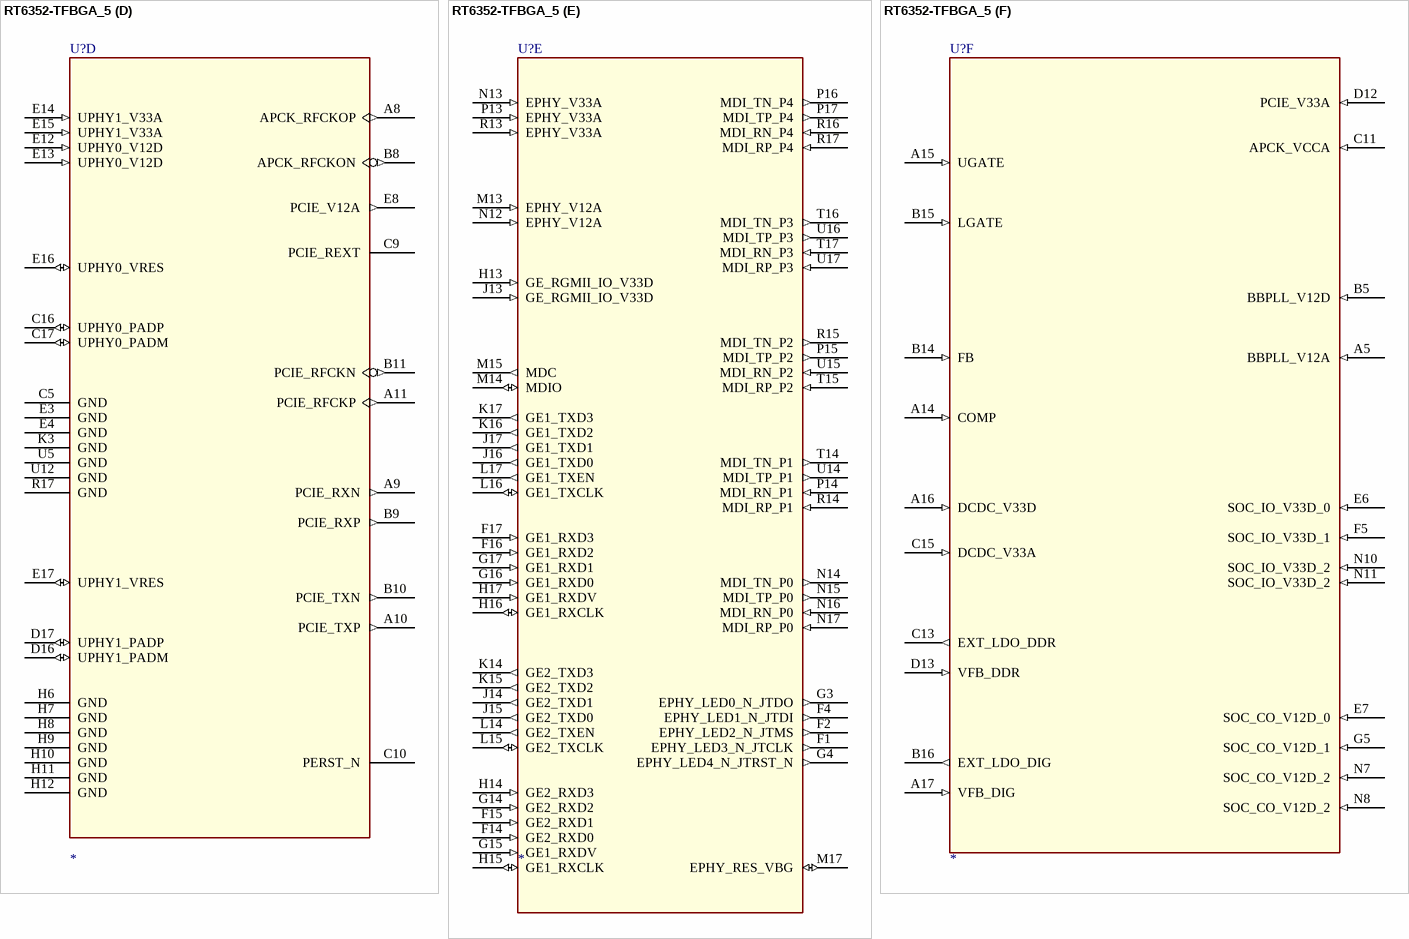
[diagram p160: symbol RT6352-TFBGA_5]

## RT6352-TFBGA_5
designator U?
footprint RT6352/BGA289/P0.65/12X12
part A pins: A1 RF0_PA2_V33P (in), A2 RF0_OUTP (out), A3 PLL_VC_CAP (out), A4 XTAL_XO (out), A6 ANT_TRN (out), B1 RF0_PA2_V33N (in), B2 RF0_OUTN (out), B3 PLL_VX_LDO (out), B4 XTAL_XI (out), B6 ANT_TRNB (out), C1 RF0_PA1_V33A (in), C2 RF1_VX_LDO (out), C3 RF0_VX_LDO (out), C4 XTAL_V12A (out), C6 PA_PE_G0 (out), D1 RF1_PA2_V33P (in), D2 RF1_PA2_V33N (in), D3 RF1_PA1_V33A (in), D4 BG_EXTR (out), D5 BG_V33A (out), D6 PA_PE_G1 (out), E1 RF1_OUTP (out), E2 RF1_OUTN (out), F3 WLED_N (out)
part B pins: F6 GND (power), F7 GND (power), F8 GND (power), F9 GND (power), F10 GND (power), F11 GND (power), F12 GND (power), G1 MD14 / MD15 (io), G2 MD9 / MD14 (io), G6 GND (power), G7 GND (power), G8 GND (power), G9 GND (power), G10 GND (power), G11 GND (power), G12 GND (power), H1 MD12 / MD13 (io), H2 MD11 / MD12 (io), H3 MRAS_N / MA5 (io), H4 MODT / MA4 (io), H5 DDR_IO_V18D/DDR_IO_V25D (in), J1 MD10 / MD11 (io), J2 MD13 / MD10 (io), J3 MCAS_N / MA7 (io), J4 MCS_N / MA6 (io), J5 DDR_IO_V18D/DDR_IO_V25D (in), K1 MD8 / MD9 (io), K2 MD15 / MD8 (io), K3 MA0 / MA8 (io), K4 MA2 / MA9 (io), K5 DDR_IOC_V12D (in), L1 MDQS1 (in), L2 MDQM1 (io), L3 MA6 / MA12 (io), L4 MA4 / MA11 (io), L5 DDR_IOC_V12D (in), M1 MCK_N (io), M2 MCK_P (io), M3 MA8 / MCKE (io), M5 MA11 / MODT (io), N1 MD5 / MD0 (io), N2 MD2 / MD1 (io), N3 MA9 / MA3 (io), N4 DDR_IO_VREF (in), N5 DDR_IO_V18D/DDR_IO_V25D (in), N6 DDR_IO_V18D/DDR_IO_V25D (in), P1 MD0 / MD2 (io), P2 MD7 / MD3 (io), P3 MA12 / MA2 (io), P4 MA7 / MA1 (io), P5 DDR_IO_VREF (in), R1 MD6 /MD4 (io), R2 MD1 / MD5 (io), R3 MA5 / MA0 (io), R4 MA3 / MA10 (io), T1 MD4 / MD6 (io), T2 MD3 / MD7 (io), T3 MA1 / MBA1 (io), T4 MBA0 / MCS_N (io), T5 MWE_N / MCAS_N (io), U1 MDQS0 (io), U2 MDQM0 (io), U3 MA10 / MBA0 (io), U4 MBA1 / MRAS_N (io), U5 MCKE / MWE_N (io)
part C pins: A7 SPI_CS0 (out), B7 SPI_CS1 (out), B17 PORST_N (in), C7 WDT_RST_N (out), C8 SPI_HOLD (out), D7 GPIO0 (io), D8 SPI_WP (out), D9 SPI_MISO (in), D10 SPI_MOSI (out), D11 SPI_CLK (out), J6 GND (power), J7 GND (power), J8 GND (power), J9 GND (power), J10 GND (power), J11 GND (power), J12 GND (power), K6 GND (power), K7 GND (power), K8 GND (power), K9 GND (power), K10 GND (power), K11 GND (power), K12 GND (power), L6 GND (power), L7 GND (power), L8 GND (power), L9 GND (power), L10 GND (power), L11 GND (power), L12 GND (power), M6 GND (power), M7 GND (power), M8 GND (power), M9 GND (power), M10 GND (power), M11 GND (power), M12 GND (power), P6 TXD2 (out), P7 RTS_N (out), P8 ND_D3/SD_D3 (out), P9 ND_D2/SD_D2 (out), P10 ND_D1/SD_D1 (out), P11 DSR_N (io), P12 RXD (io), R6 RXD2 (in), R7 ND_D5/bt_aux (out), R8 ND_CS_N (out), R9 ND_WP/SD_WP (out), R10 ND_D0/SD_D0 (out), R11 DCD_N (io), R12 RIN (io), T6 I2C_SD (out), T7 ND_D6/bt_wact (out), T8 ND_CLE/SD_card_detect, T9 ND_WE_N (out), T10 ND_ALE/SD_CMD (out), T11 TXD (out), T12 CTS_N (io), U6 I2C_SCLK (io), U7 ND_D7/bt_ant (out), U8 ND_D4/bt_stat (out), U9 ND_RE_N (out), U10 ND_RB_N/SD_CLK (out), U11 DTR_N (out)
part D pins: A8 APCK_RFCKOP (out), A9 PCIE_RXN (out), A10 PCIE_TXP (out), A11 PCIE_RFCKP (out), B8 APCK_RFCKON (out), B9 PCIE_RXP (out), B10 PCIE_TXN (out), B11 PCIE_RFCKN (out), C5 GND (power), C9 PCIE_REXT, C10 PERST_N, C16 UPHY0_PADP (io), C17 UPHY0_PADM (io), D16 UPHY1_PADM (io), D17 UPHY1_PADP (io), E3 GND (power), E4 GND (power), E8 PCIE_V12A (out), E12 UPHY0_V12D (in), E13 UPHY0_V12D (in), E14 UPHY1_V33A (in), E15 UPHY1_V33A (in), E16 UPHY0_VRES (io), E17 UPHY1_VRES (io), H6 GND (power), H7 GND (power), H8 GND (power), H9 GND (power), H10 GND (power), H11 GND (power), H12 GND (power), K3 GND (power), R17 GND (power), U5 GND (power), U12 GND (power)
part E pins: F1 EPHY_LED3_N_JTCLK (out), F2 EPHY_LED2_N_JTMS (out), F4 EPHY_LED1_N_JTDI (out), F14 GE2_RXD0 (in), F15 GE2_RXD1 (in), F16 GE1_RXD2 (in), F17 GE1_RXD3 (in), G3 EPHY_LED0_N_JTDO (out), G4 EPHY_LED4_N_JTRST_N (out), G14 GE2_RXD2 (in), G15 GE1_RXDV (in), G16 GE1_RXD0 (in), G17 GE1_RXD1 (in), H13 GE_RGMII_IO_V33D (in), H14 GE2_RXD3 (in), H15 GE1_RXCLK (io), H16 GE1_RXCLK (io), H17 GE1_RXDV (in), J13 GE_RGMII_IO_V33D (in), J14 GE2_TXD1 (out), J15 GE2_TXD0 (out), J16 GE1_TXD0 (out), J17 GE1_TXD1 (out), K14 GE2_TXD3 (out), K15 GE2_TXD2 (out), K16 GE1_TXD2 (out), K17 GE1_TXD3 (out), L14 GE2_TXEN (out), L15 GE2_TXCLK (io), L16 GE1_TXCLK (io), L17 GE1_TXEN (out), M13 EPHY_V12A (in), M14 MDIO (io), M15 MDC (out), M17 EPHY_RES_VBG (io), N12 EPHY_V12A (in), N13 EPHY_V33A (in), N14 MDI_TN_P0 (out), N15 MDI_TP_P0 (out), N16 MDI_RN_P0 (in), N17 MDI_RP_P0 (in), P13 EPHY_V33A (in), P14 MDI_RN_P1 (in), P15 MDI_TP_P2 (out), P16 MDI_TN_P4 (out), P17 MDI_TP_P4 (out), R13 EPHY_V33A (in), R14 MDI_RP_P1 (in), R15 MDI_TN_P2 (out), R16 MDI_RN_P4 (in), R17 MDI_RP_P4 (in), T14 MDI_TN_P1 (out), T15 MDI_RP_P2 (in), T16 MDI_TN_P3 (out), T17 MDI_RN_P3 (in), U14 MDI_TP_P1 (out), U15 MDI_RN_P2 (in), U16 MDI_TP_P3 (out), U17 MDI_RP_P3 (in)
part F pins: A5 BBPLL_V12A (in), A14 COMP (in), A15 UGATE (in), A16 DCDC_V33D (in), A17 VFB_DIG (in), B5 BBPLL_V12D (in), B14 FB (in), B15 LGATE (in), B16 EXT_LDO_DIG (out), C11 APCK_VCCA (in), C13 EXT_LDO_DDR (out), C15 DCDC_V33A (in), D12 PCIE_V33A (in), D13 VFB_DDR (in), E6 SOC_IO_V33D_0 (in), E7 SOC_CO_V12D_0 (in), F5 SOC_IO_V33D_1 (in), G5 SOC_CO_V12D_1 (in), N7 SOC_CO_V12D_2 (in), N8 SOC_CO_V12D_2 (in), N10 SOC_IO_V33D_2 (in), N11 SOC_IO_V33D_2 (in)

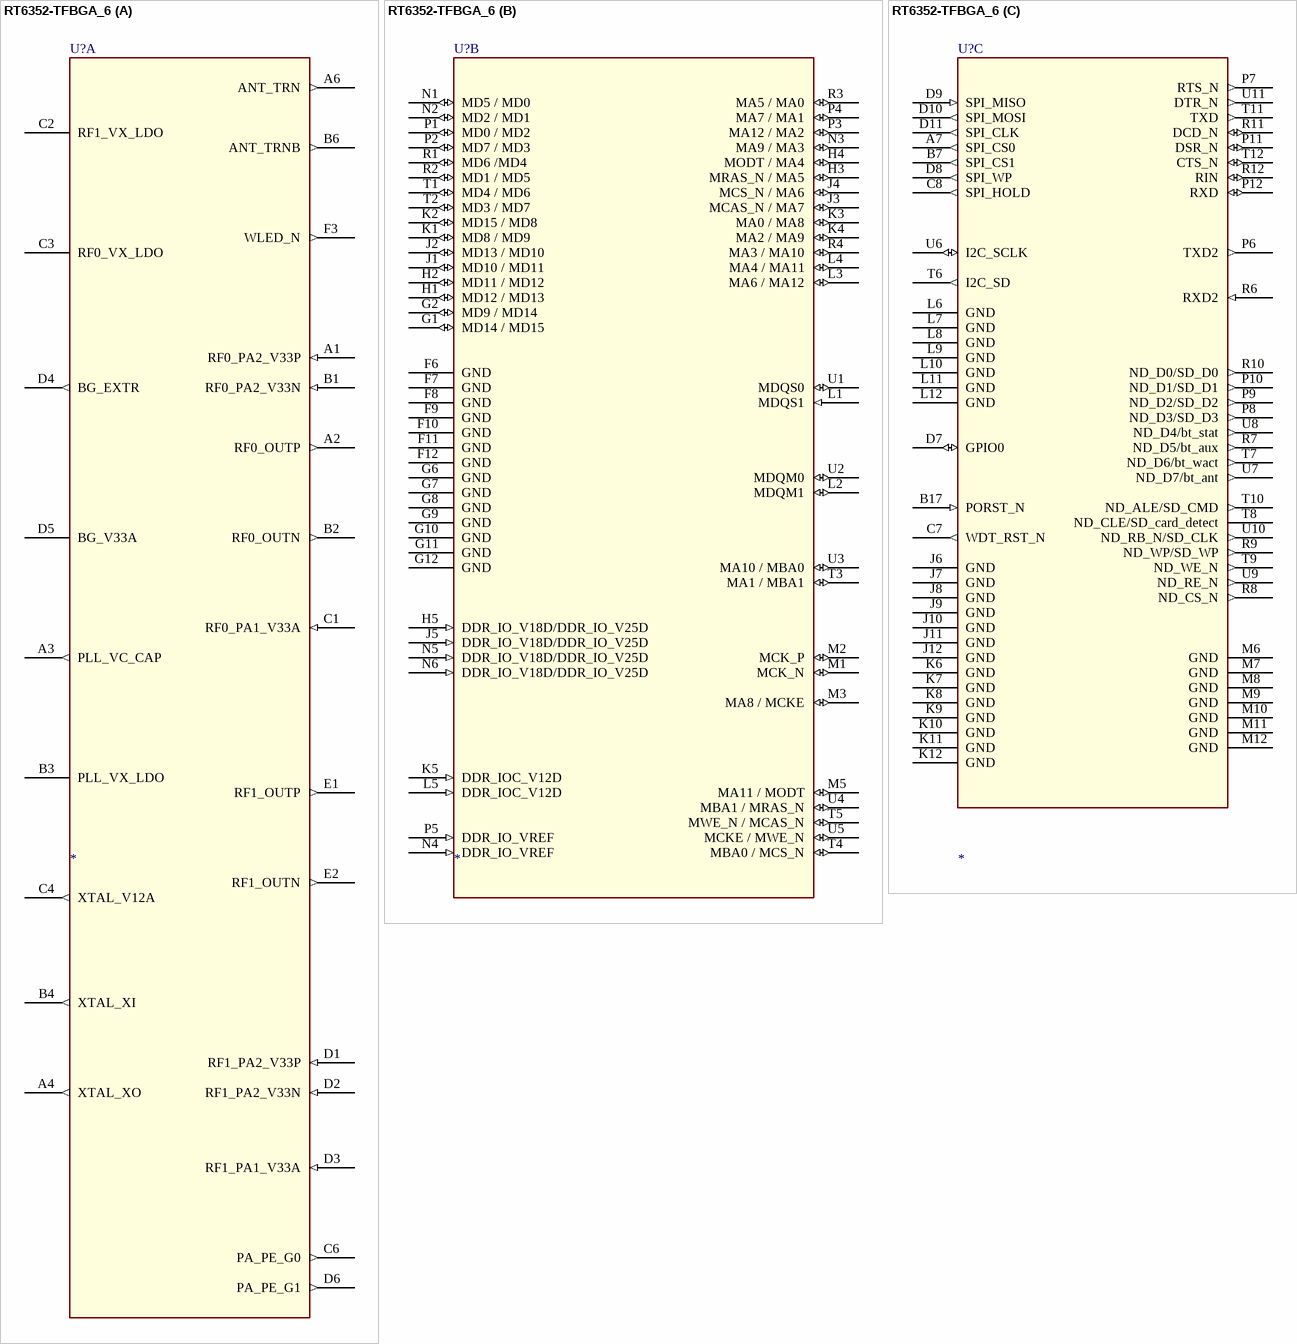
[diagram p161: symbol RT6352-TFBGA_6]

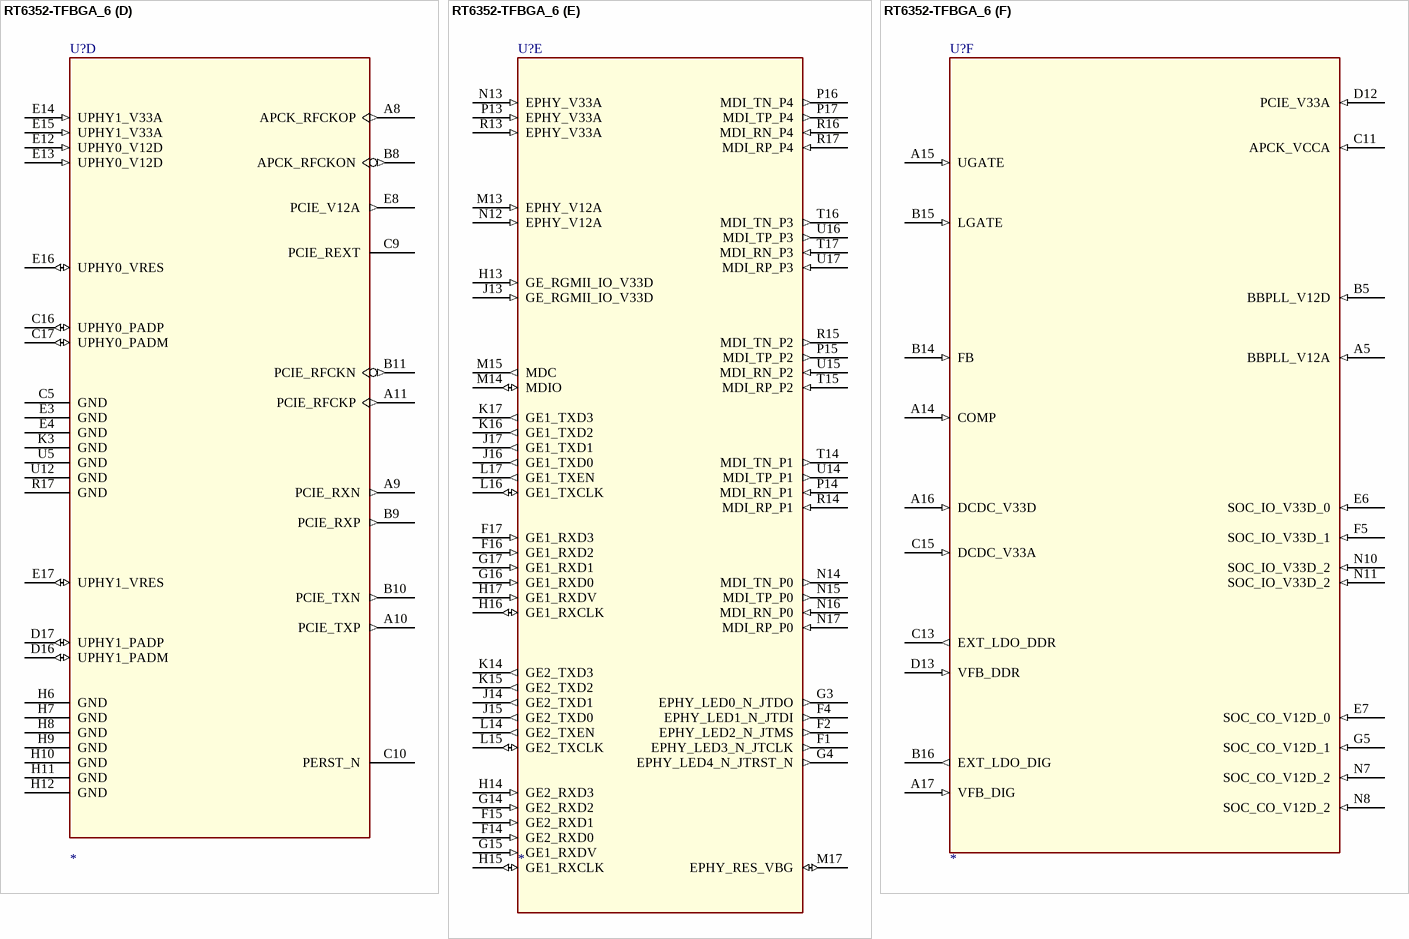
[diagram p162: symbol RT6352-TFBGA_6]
